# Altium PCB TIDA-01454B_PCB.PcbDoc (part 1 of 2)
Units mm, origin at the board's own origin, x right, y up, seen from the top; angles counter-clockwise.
Board outline 75 x 75 mm, 6 copper layers (Top Copper, Copper Layer 2, Copper Layer 3, Copper Layer 4, Copper Layer 5, Bottom Copper), stack 1.56 mm thick; 207 components, 118 nets, 481 pads, 110 vias.
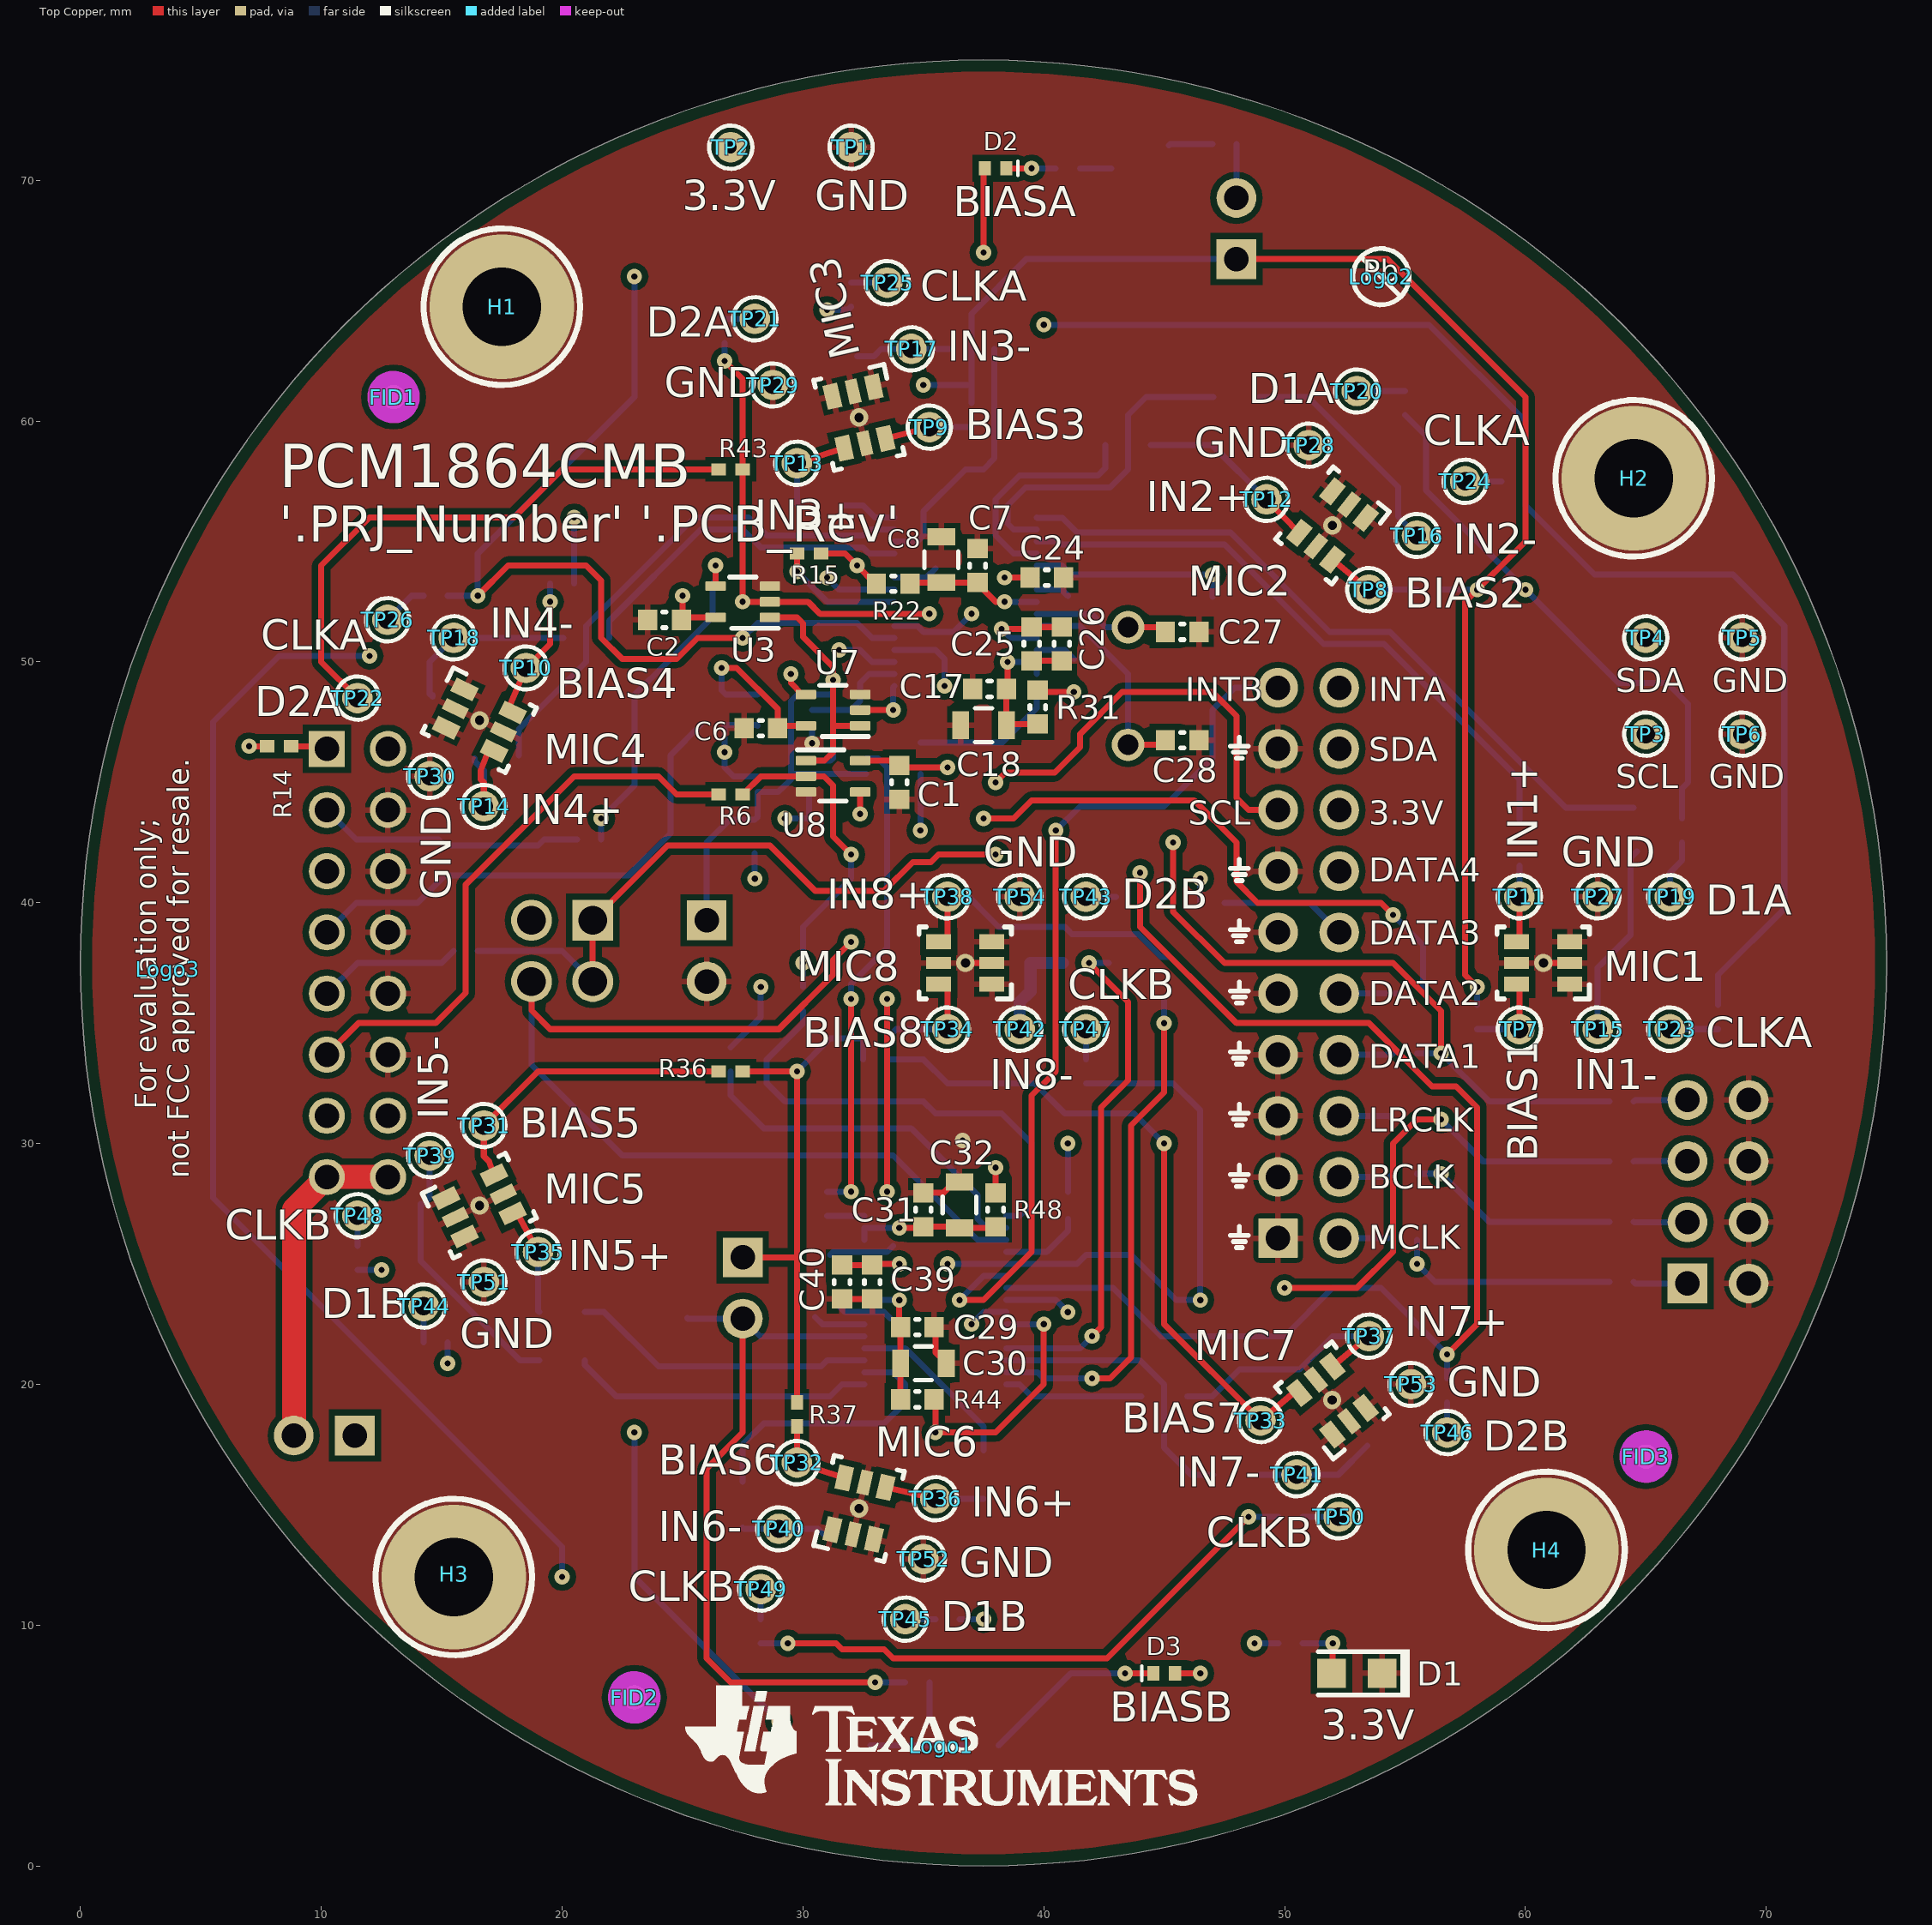
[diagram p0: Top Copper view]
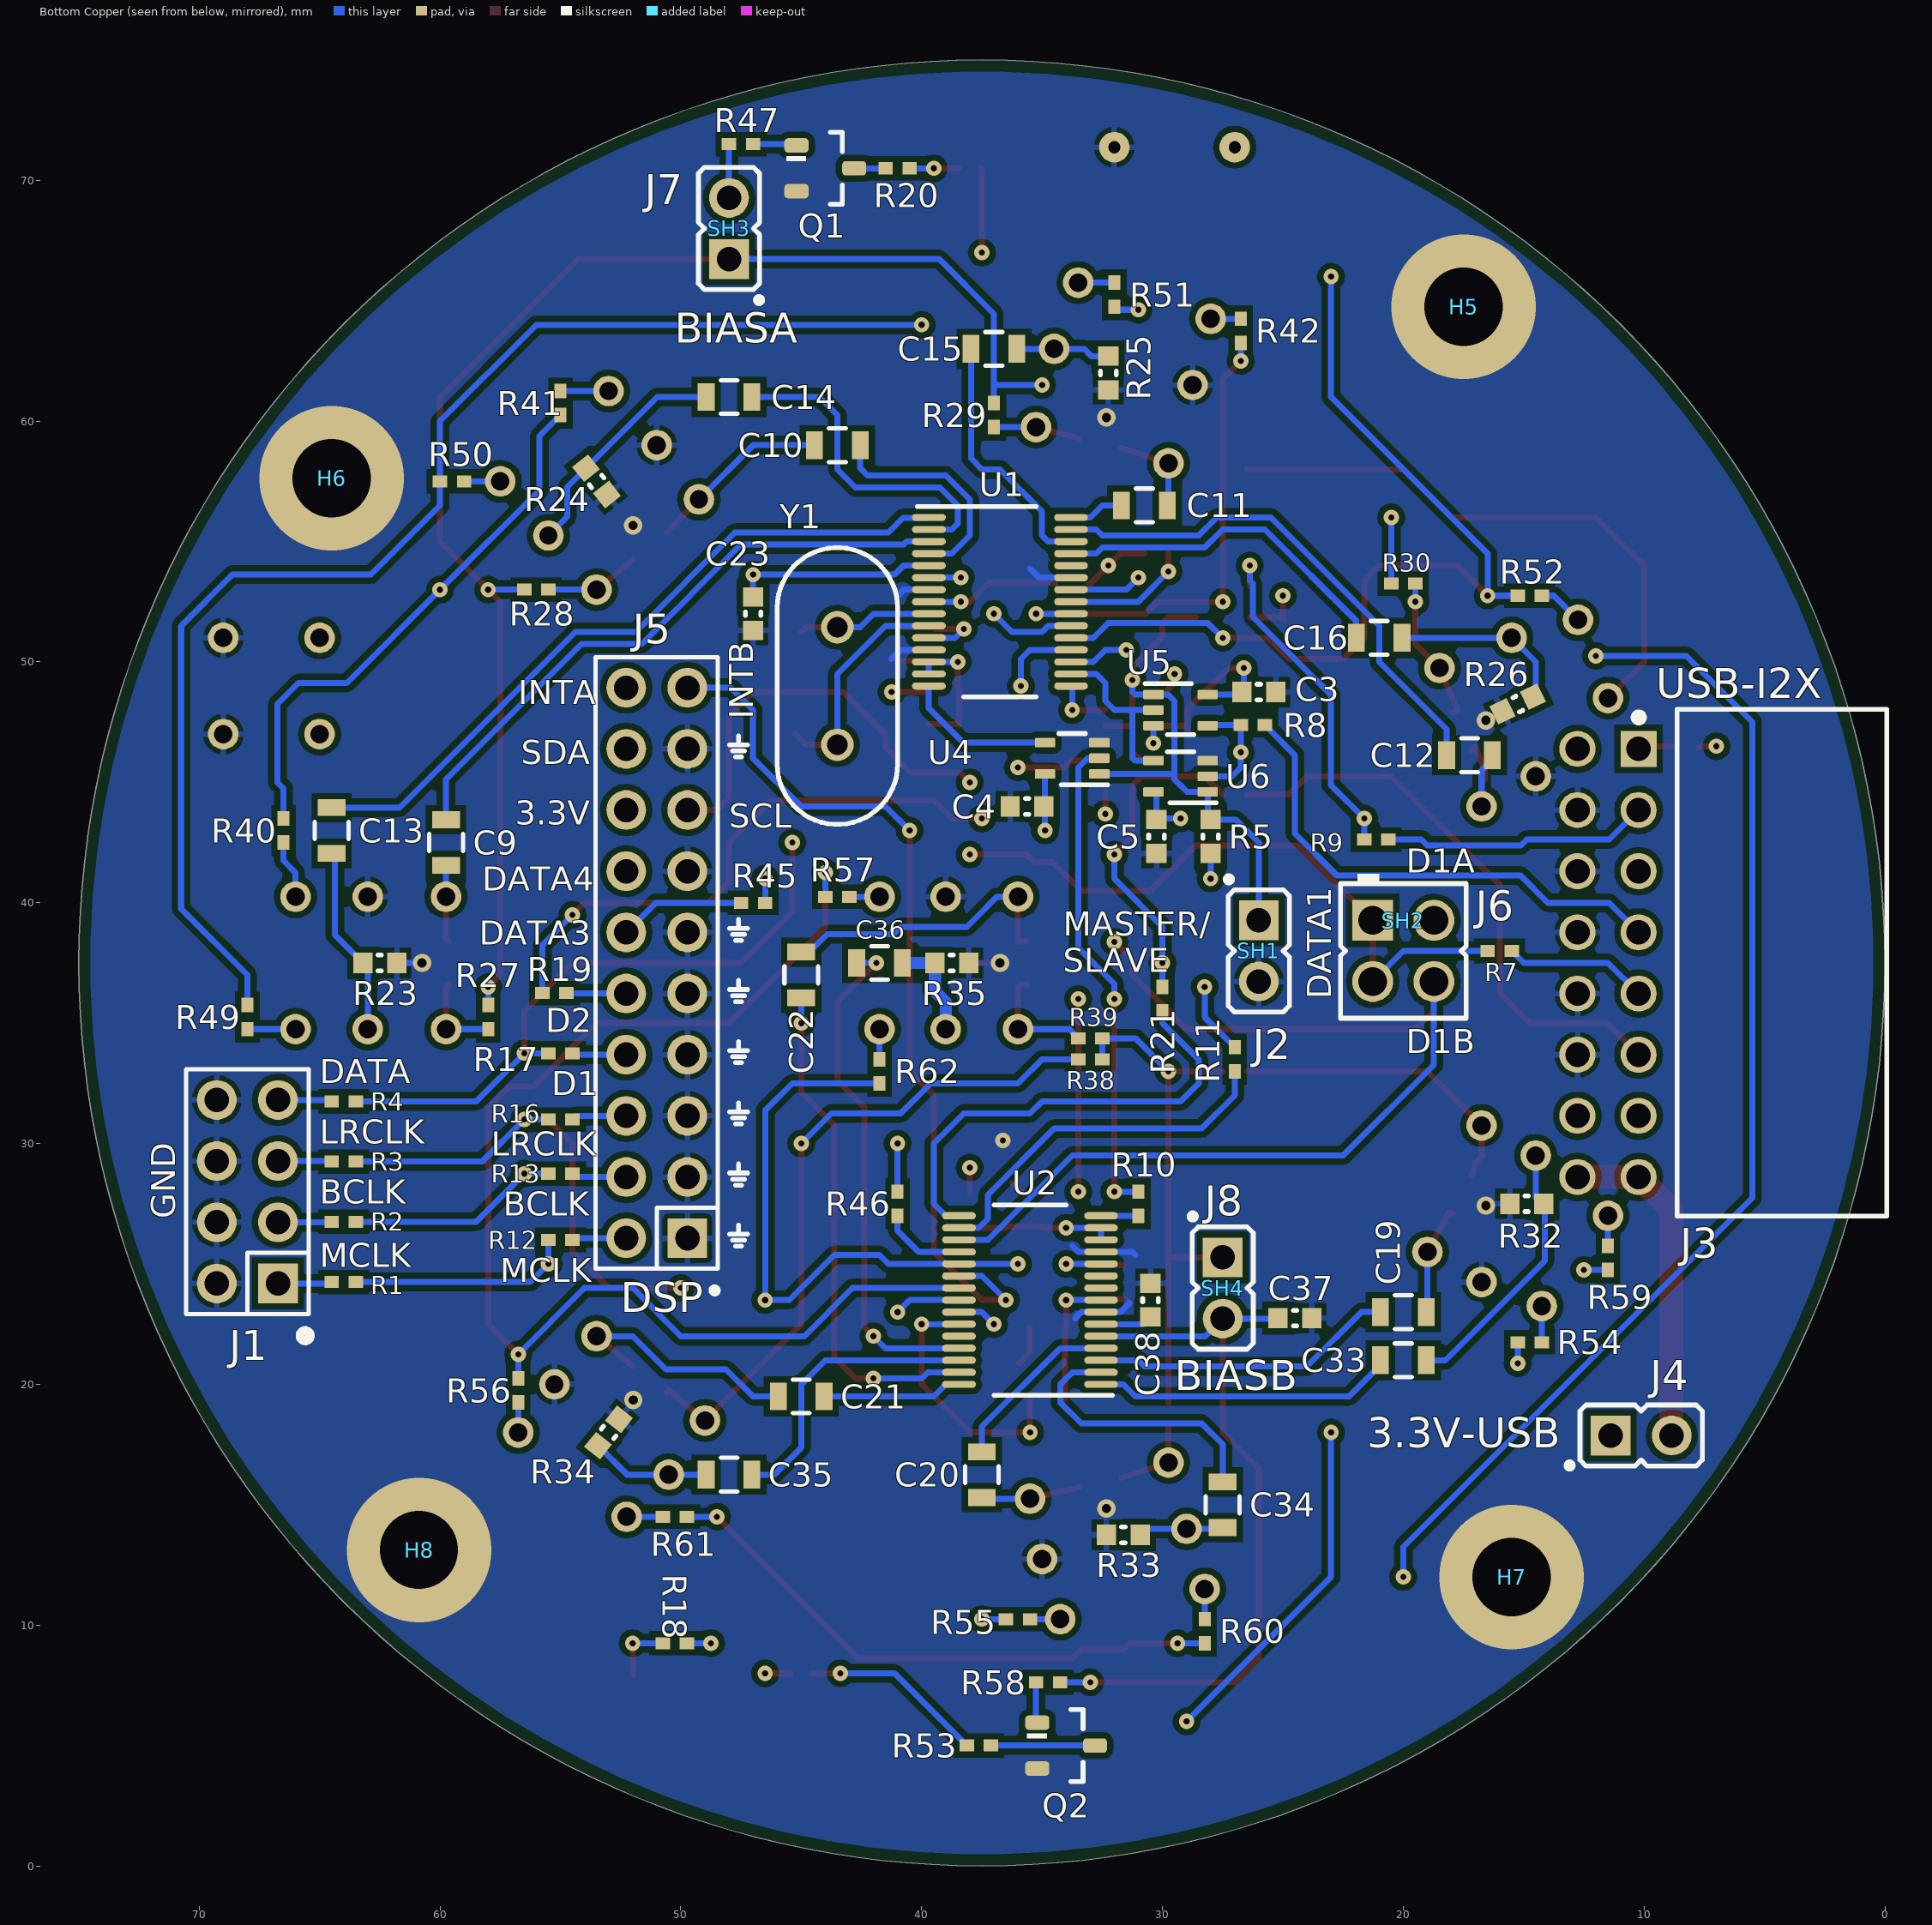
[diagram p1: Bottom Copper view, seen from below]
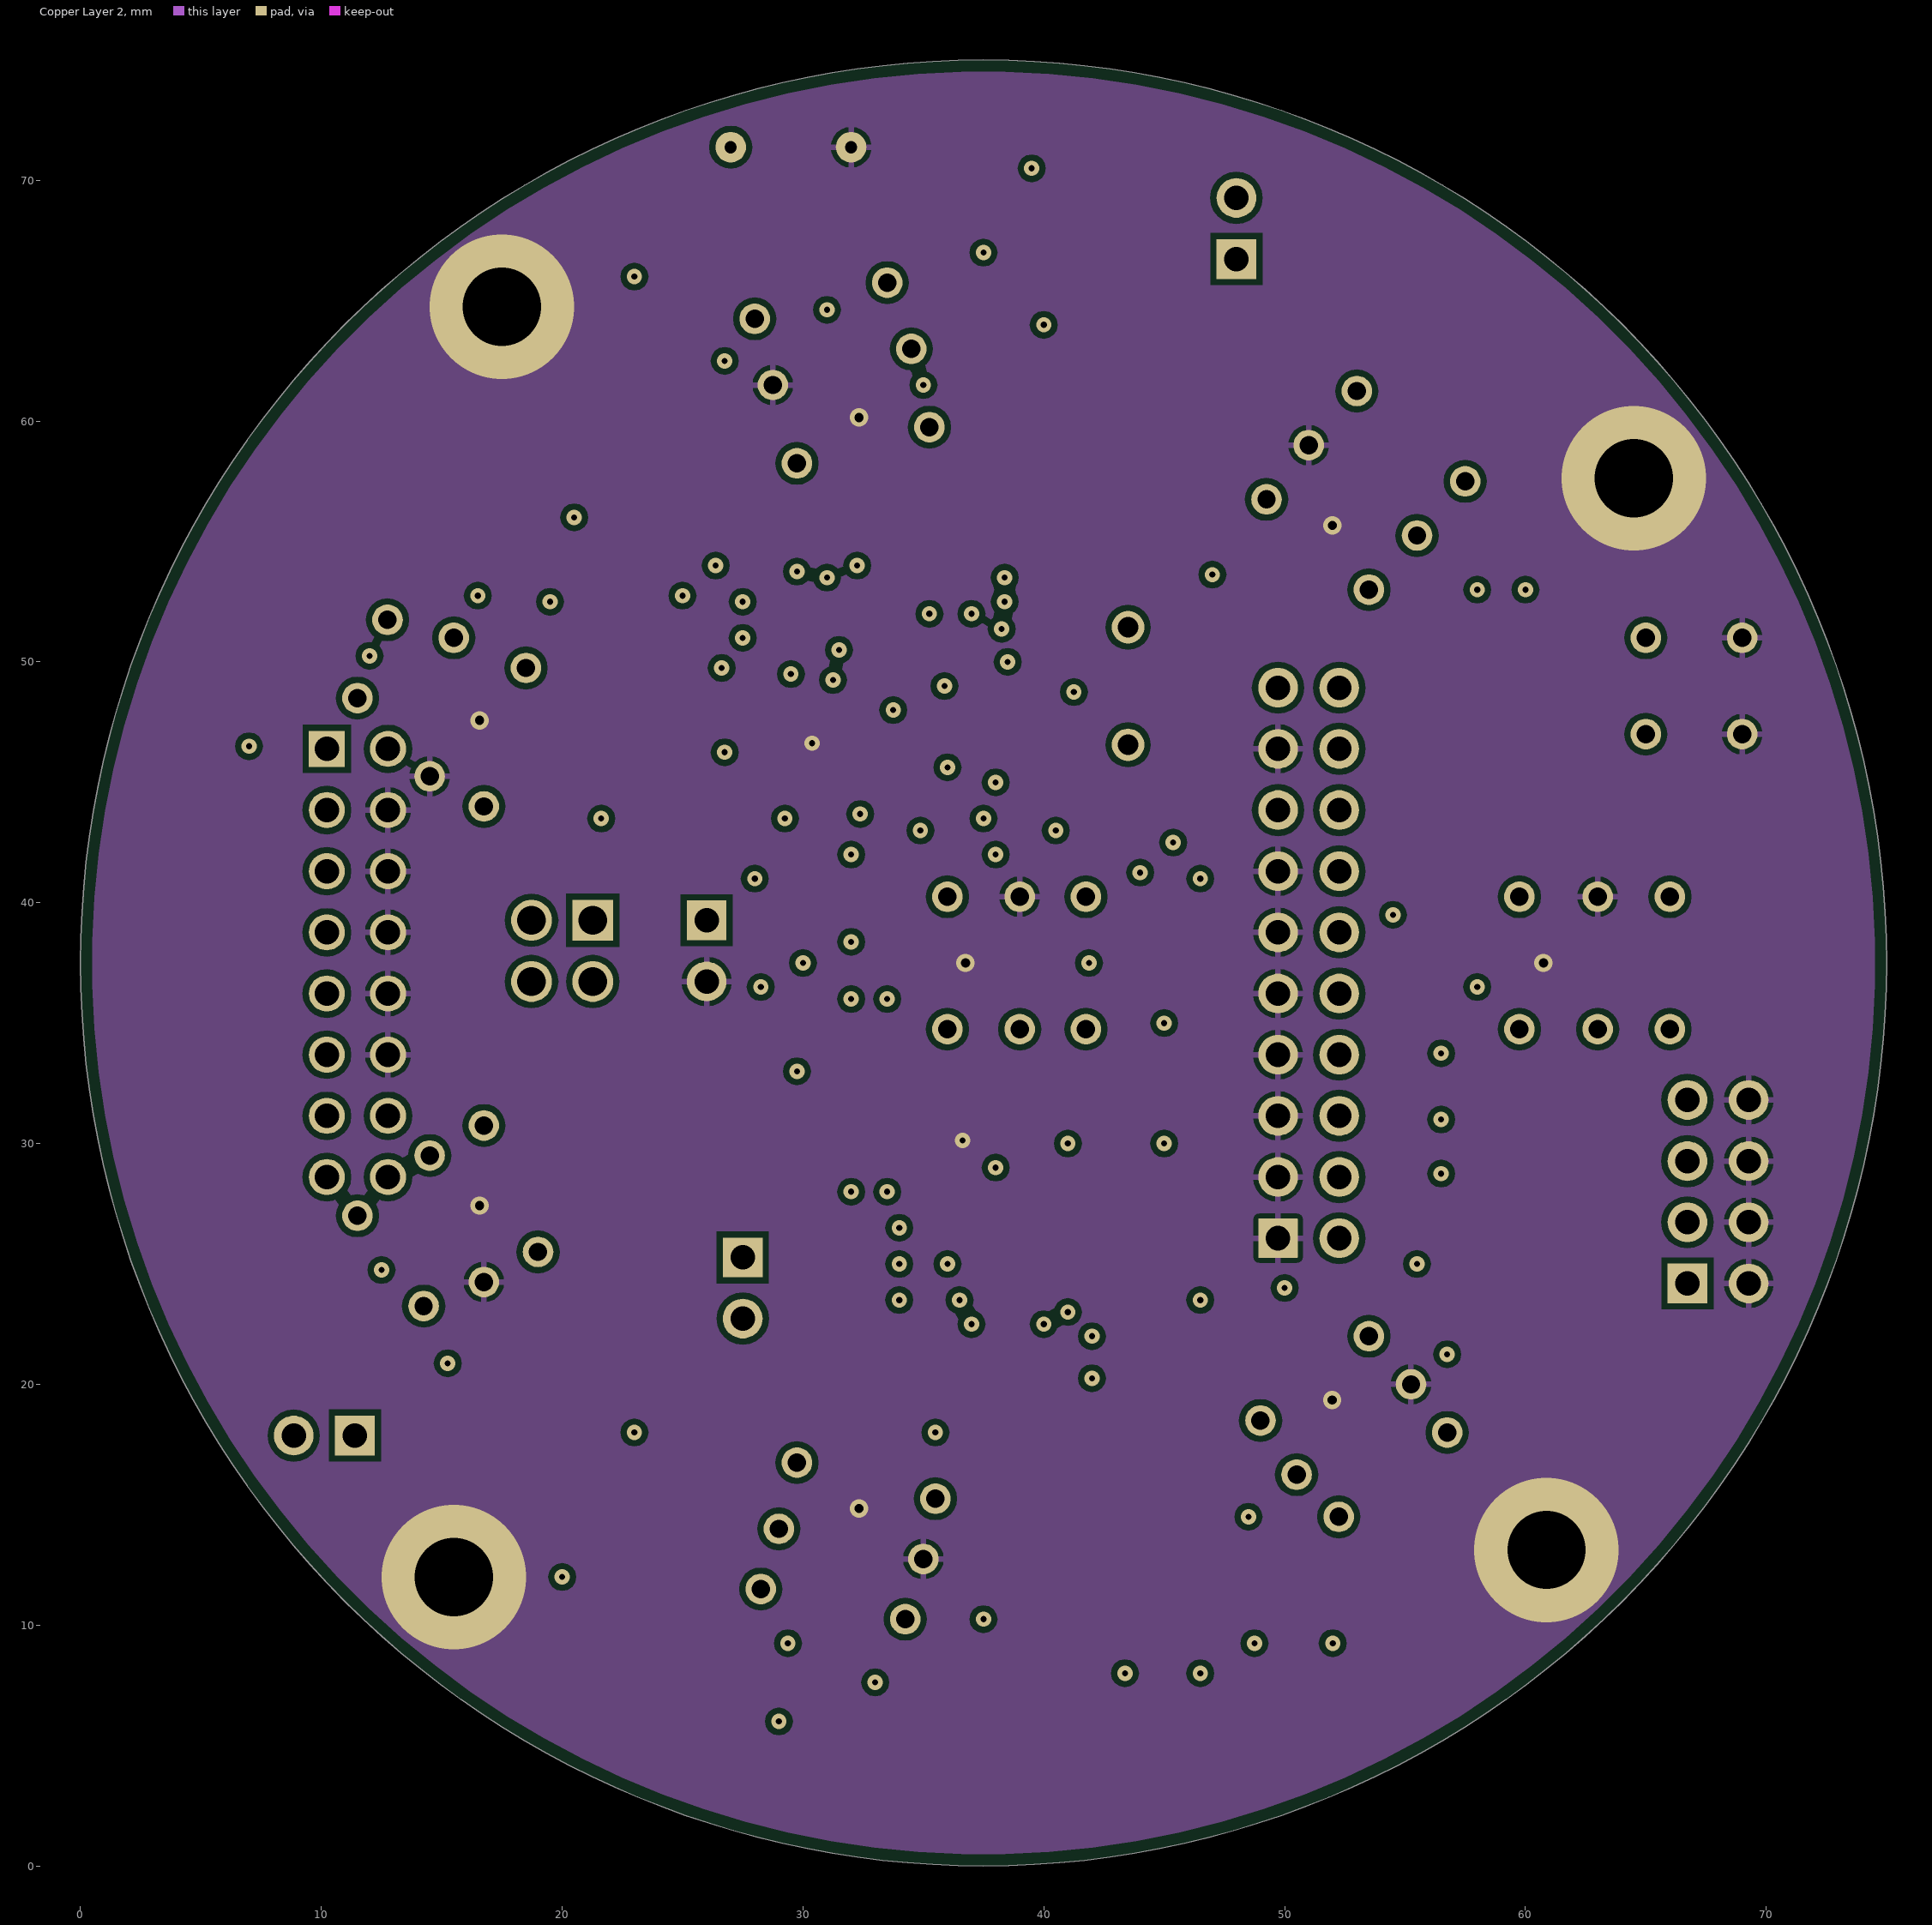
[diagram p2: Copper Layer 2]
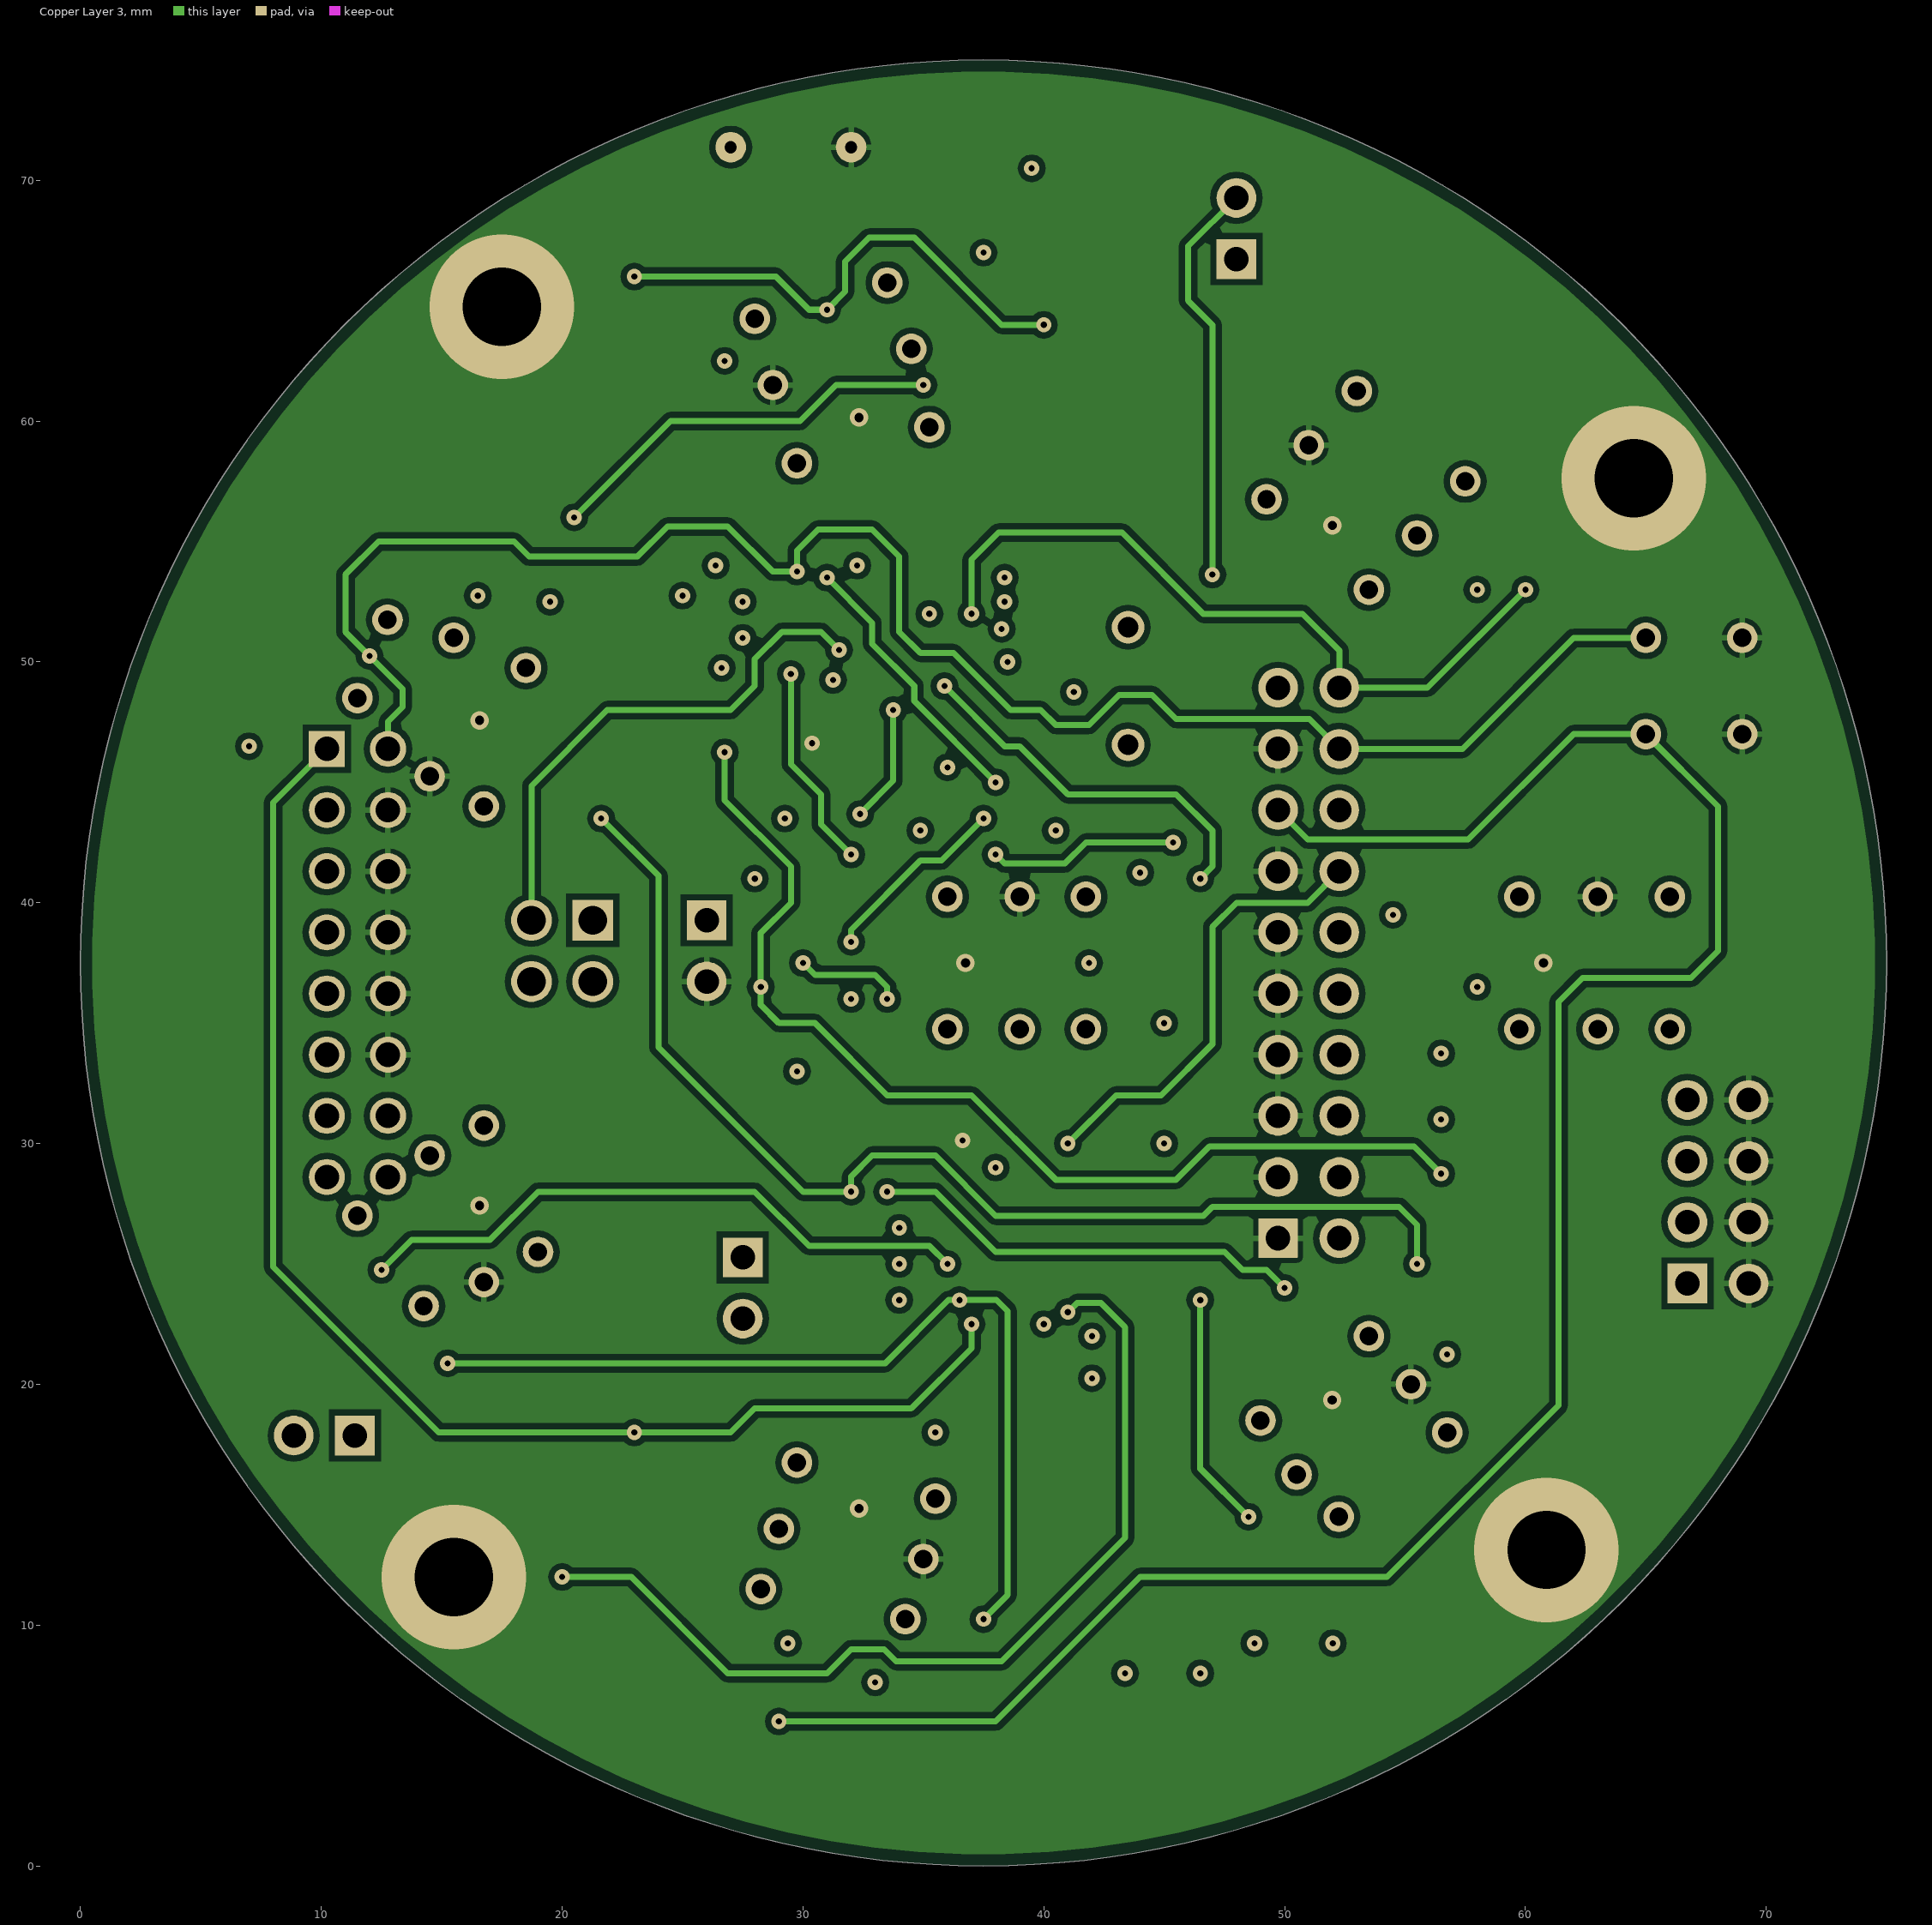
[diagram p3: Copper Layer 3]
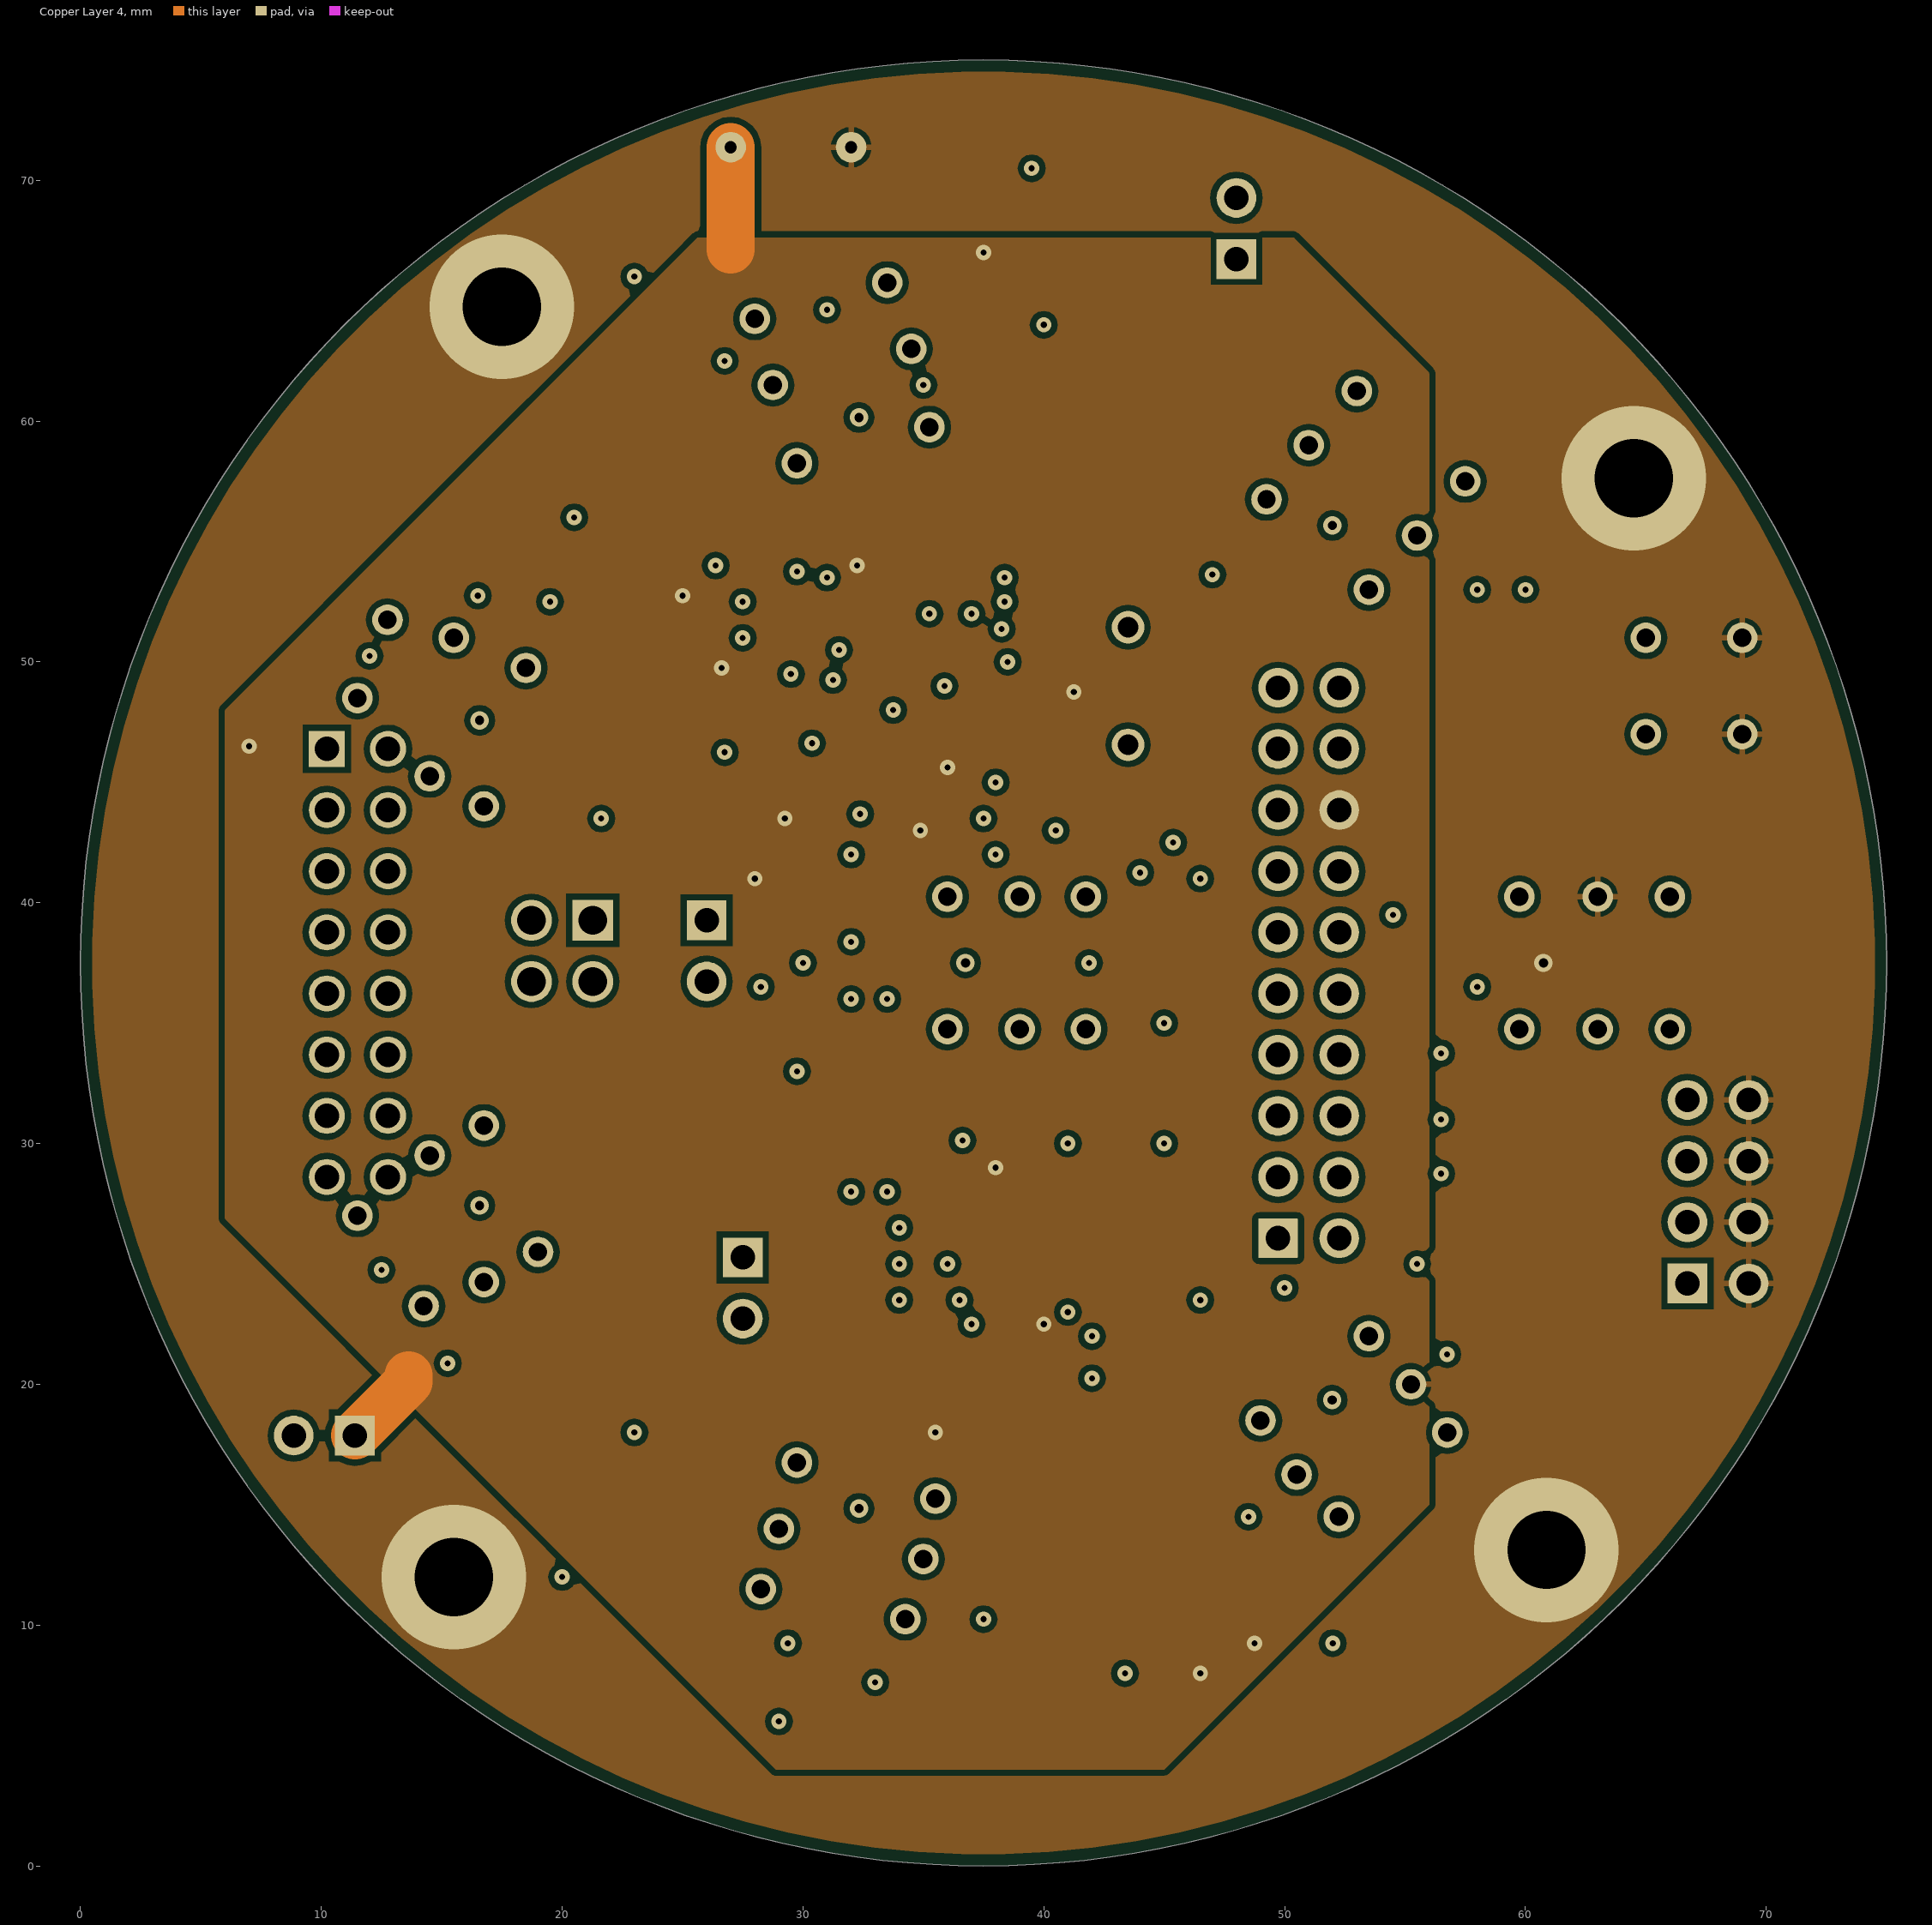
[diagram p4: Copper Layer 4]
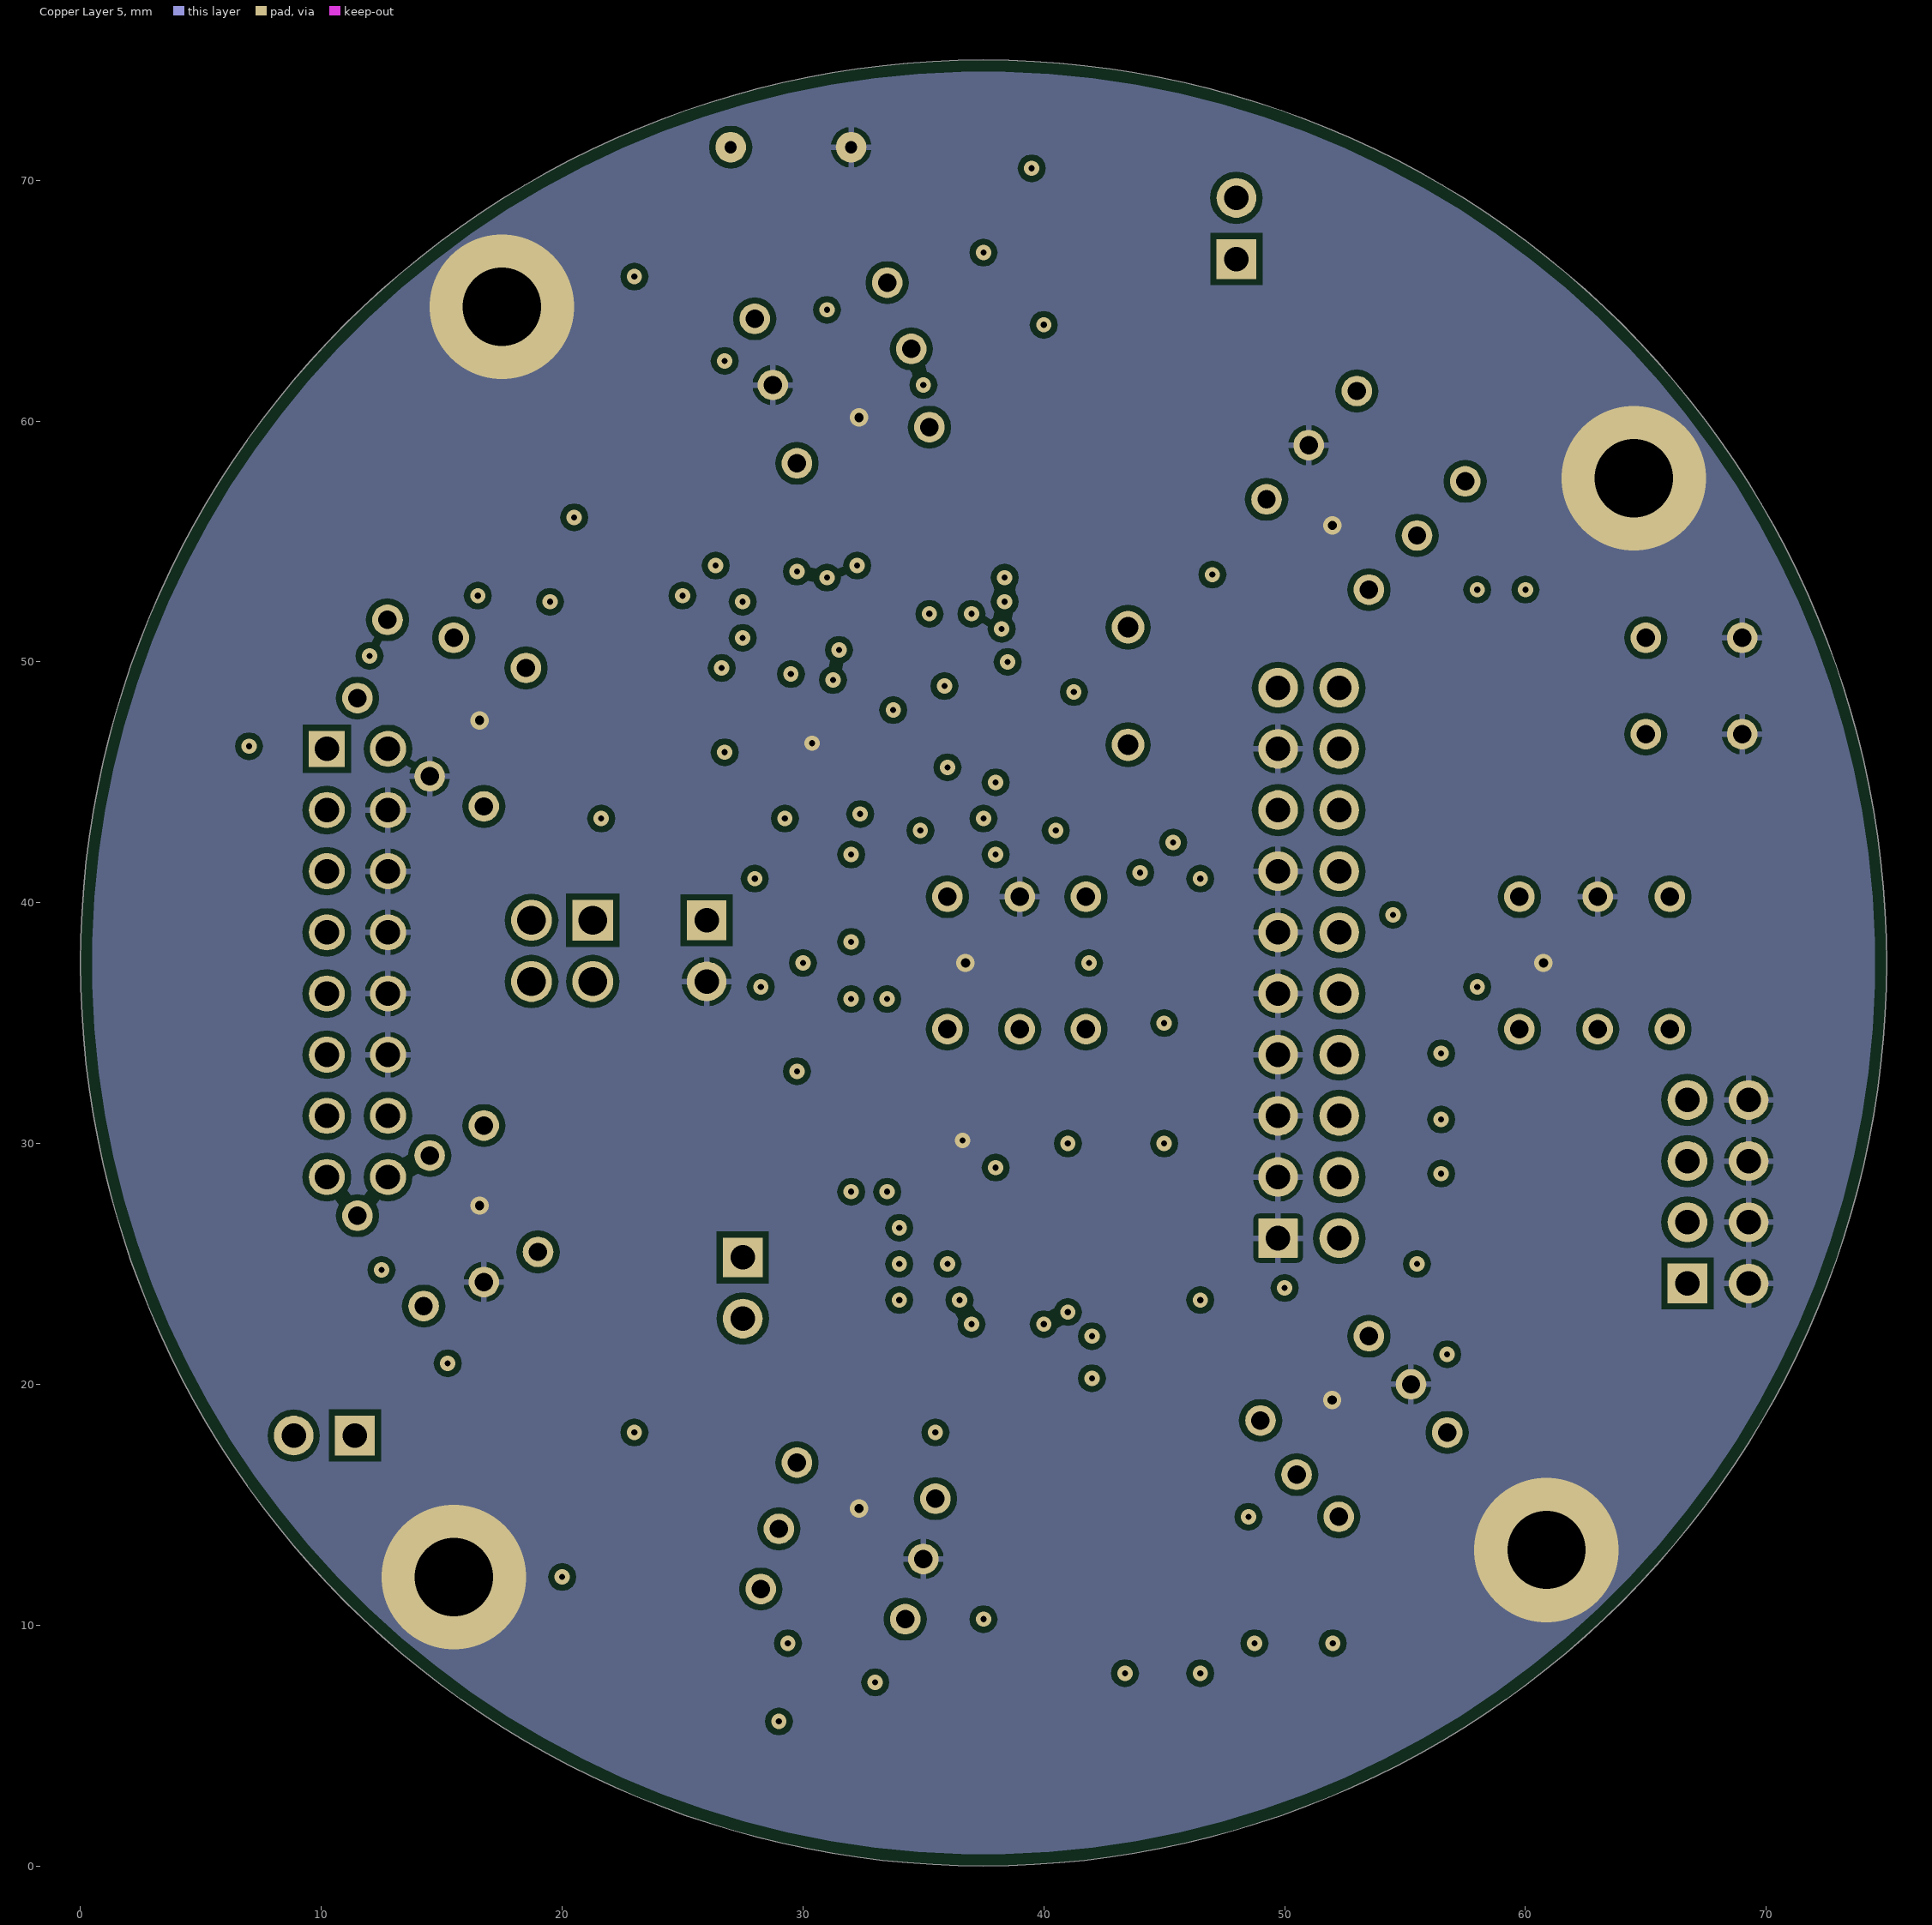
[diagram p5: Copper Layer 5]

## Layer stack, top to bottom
Top Solder Mask: solder mask 0.0127, Solder Resist, Dk 3.5
Top Copper: signal copper 0.0356
Dielectric 1: prepreg 0.1778, FR-4, Dk 4.2
Copper Layer 2: signal copper 0.0356
Dielectric 2: core 0.3556, FR-4, Dk 4.2
Copper Layer 3: signal copper 0.0356
Dielectric 4: prepreg 0.2794, FR-4, Dk 4.2
Copper Layer 4: signal copper 0.0356
Dielectric 5: core 0.3556, FR-4, Dk 4.2
Copper Layer 5: signal copper 0.0356
Dielectric 3: prepreg 0.1778, FR-4, Dk 4.2
Bottom Copper: signal copper 0.0356
Bottom Solder Mask: solder mask 0.0127, Solder Resist, Dk 3.5

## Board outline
37.5,0 cw(c37.5,37.5) 0,37.5 cw(c37.5,37.5) 37.5,75 cw(c37.5,37.5) 75,37.5 cw(c37.5,37.5)

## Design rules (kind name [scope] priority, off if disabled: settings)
AcuteAngle [All] p1: minimum=4.50000000000000E+0001 checktracksonly=FALSE
AssemblyTestPointUsage [All] p1: valid=2
BoardOutlineClearance BoardOutlineClearance_MountingHoles [OnCopper and InComponentClass('Mounting Holes')] p1: gap=1.016
BoardOutlineClearance BoardOutlineClearance_Poly [OnCopper and IsPoly] p2: gap=0.25
BoardOutlineClearance [OnCopper and Not InComponentClass('Logo') and not InComponentClass('FiducialMark') and not InRegion(1000,500,4000,800) and not InPoly] p3: gap=0.25
Clearance Clearance_Keepouts [((IsTrack Or IsArc) And Not InPoly) And IsFree and IsKeepOut vs ((IsTrack Or IsArc) And Not InPoly) And IsFree and IsKeepOut] p1: gap=0
Clearance Clearance_Poly [InPolygon] p2: gap=0.25
Clearance [All] p3: gap=0.2
ComponentClearance ComponentClearance_MountingHoles_FiducialMarks [InComponentClass('Mounting Holes') vs InComponentClass('FiducialMark')] p1: gap=1.27 collisioncheckmode=3 verticalgap=0.254 showdistances=FALSE
ComponentClearance ComponentClearance_Shunt [InComponentClass('Header') vs InComponentClass('Shunt')] p2: gap=0 collisioncheckmode=3 verticalgap=0 showdistances=FALSE
ComponentClearance ComponentClearance_Logo [InComponentClass('Logo')] p3: gap=0 collisioncheckmode=3 verticalgap=0 showdistances=FALSE
ComponentClearance ComponentClearance_ScrewToNut [(HasFootprint('NY PMS 440 0025 PH')) vs (HasFootprint('Keystone_1902C'))] p4: gap=0.127 collisioncheckmode=3 verticalgap=0.254 showdistances=FALSE
ComponentClearance ComponentClearance_MountingHoles [InComponentClass('Hardware') vs InComponentClass('Hardware')] p5: gap=0 collisioncheckmode=3 verticalgap=0 showdistances=FALSE
ComponentClearance ComponentClearance_SmallPassives [HasFootprint('0201*') or HasFootprint('0402*') or HasFootprint('0508') or HasFootprint('0603*') or HasFootprint('0612') or HasFootprint('0805*') or HasFootprint('0815*') or HasFootprint('0830*') or HasFootprint('1206*') or HasFootprint('1210*') or HasFootprint('1808*') or HasFootprint('1812*') or HasFootprint('1825*') or HasFootprint('2010*') or HasFootprint('2220*') or HasFootprint('2225*') or HasFootprint('2512*') or HasFootprint('2728*') or HasFootprint('3518*') or HasFootprint('DCK*') vs HasFootprint('0201*') or HasFootprint('0402*') or HasFootprint('0508') or HasFootprint('0603*') or HasFootprint('0612') or HasFootprint('0805*') or HasFootprint('0815*') or HasFootprint('0830*') or HasFootprint('1206*') or HasFootprint('1210*') or HasFootprint('1808*') or HasFootprint('1812*') or HasFootprint('1825*') or HasFootprint('2010*') or HasFootprint('2220*') or HasFootprint('2225*') or HasFootprint('2512*') or HasFootprint('2728*') or HasFootprint('3518*') or HasFootprint('DCK*')] p6: gap=0.25 collisioncheckmode=3 verticalgap=0 showdistances=FALSE
ComponentClearance ComponentClearance_THtoSMT [IsThruComponent vs IsSMTComponent] p7: gap=0.25 collisioncheckmode=3 verticalgap=0 showdistances=FALSE
ComponentClearance ComponentClearance_THtoTH [IsThruComponent vs IsThruComponent] p8: gap=0.762 collisioncheckmode=3 verticalgap=0.762 showdistances=FALSE
ComponentClearance [All] p9: gap=0.762 collisioncheckmode=3 verticalgap=0.254 showdistances=FALSE
DiffPairsRouting [All] p1: maxlimit=2.54 minlimit=0.254 mostfreqgap=0.254 toplayer_minwidth=0.381 toplayer_maxwidth=0.381 toplayer_prefwidth=0.381 midlayer1_minwidth=0.381 midlayer1_maxwidth=0.381 midlayer1_prefwidth=0.381 midlayer2_minwidth=0.381 midlayer2_maxwidth=0.381 midlayer2_prefwidth=0.381 midlayer3_minwidth=0.381 midlayer3_maxwidth=0.381 midlayer3_prefwidth=0.381 midlayer4_minwidth=0.381 midlayer4_maxwidth=0.381 midlayer4_prefwidth=0.381 bottomlayer_minwidth=0.381 bottomlayer_maxwidth=0.381 bottomlayer_prefwidth=0.381 maxuncoupledlength=25.4
FabricationTestPointUsage TestPointUsage [All] p1: valid=2 allowmultiple=FALSE
FabricationTestpoint Testpoint [All] p1: side=3 testpointundercomponent=TRUE minsize=1.016 maxsize=2.54 preferedsize=1.524 minholesize=0 maxholesize=1.016 preferedholesize=0.813 testpointgrid=0.025 allowsidetop=TRUE allowsidebottom=TRUE usegrid=TRUE gridtolerance=0
FanoutControl Fanout_LCC [IsLCC] p1: bgadir=Out bgaviamode=Centered fanoutstyle=Auto fanoutdirection=Alternating viagrid=0.025 // Fanout_LCC (Default Rule)
FanoutControl Fanout_BGA [IsBGA] p2: bgadir=Out bgaviamode=Centered fanoutstyle=Auto fanoutdirection=Alternating viagrid=0.025 // Fanout_BGA (Default Rule)
FanoutControl Fanout_Default [All] p4: bgadir=Out bgaviamode=Centered fanoutstyle=Auto fanoutdirection=Alternating viagrid=0.025 // Fanout_Default (Default Rule)
FanoutControl Fanout_Small [(CompPinCount < 5)] p5: bgadir=Out bgaviamode=Centered fanoutstyle=Auto fanoutdirection=OutThenIn viagrid=0.025 // Fanout_Small (Default Rule)
HoleSize [All] p1: absolutevalues=TRUE maxlimit=6.375 minlimit=0.2 maxpercent=80.000 minpercent=20.000
MinimumAnnularRing MinimumAnnularRing_ThermalPadVias [IsVia and InAnyComponent] p1: minimumring=0.15
MinimumAnnularRing [All] p2: minimumring=0.127
MinimumSolderMaskSliver MinimumSolderMaskSliver_Logo [InComponentClass('Logo') vs InComponentClass('Logo')] p1: minsoldermaskwidth=0.018
MinimumSolderMaskSliver [All] p2: minsoldermaskwidth=0.089
PlaneConnect [All] p1: planeconnectstyle=Relief reliefexpansion=0.254 reliefentries=4 reliefconductorwidth=0.254 reliefairgap=0.254
PolygonConnect "GND Thermals 0.25mm" [(InComponent('BIAS*') or InComponent('C*') or InComponent('D*') or InComponent('GND*') or InComponent('I2S*') or InComponent('J*') or InComponent('MIC*') or InComponent('R*') or InComponent('TP*') or InComponent('USB-I2X')) vs InNet('GND')] p1: connectstyle=Relief reliefconductorwidth=0.25 reliefentries=4 polygonreliefangle="90 Angle" airgapwidth=0.2
PolygonConnect PreFlood [All] p2: connectstyle=Direct reliefconductorwidth=0.254 reliefentries=4 polygonreliefangle="90 Angle" airgapwidth=0.254
RoutingVias ThermalPadVias [IsVia and InAnyComponent] p1: holewidth=0.2 width=0.5 viastyle="Through Hole" minholewidth=0.2 minwidth=0.5 maxholewidth=0.33 maxwidth=0.6
RoutingVias [All] p2: holewidth=0.254 width=0.635 viastyle="Through Hole" minholewidth=0.254 minwidth=0.508 maxholewidth=3.25 maxwidth=6
SilkToBoardRegionClearance [Not ((IsComment or IsDesignator) And (Hide <> 'False')) and not InRegion(1000,500,4000,800)] p1:
SilkToSilkClearance SilkToSilkClearance_Pb-FreeLogo [(HasFootprint('Pb-Free_Overlay_Medium') OR HasFootprint('Pb-Free_Overlay_Small')) vs (HasFootprint('Pb-Free_Overlay_Medium') OR HasFootprint('Pb-Free_Overlay_Small'))] p1: silktosilkclearance=0
SilkToSilkClearance [All] p2: silktosilkclearance=0.127
SilkToSolderMaskClearance SilkToComponentPadClearance [IsPad and InAnycomponent] p1: minsilkscreentomaskgap=0.127 clearancetoexposedcopper=TRUE
SilkToSolderMaskClearance "Silk to Solder Mask Opening" [All] p2: minsilkscreentomaskgap=0.127 clearancetoexposedcopper=FALSE
SolderMaskExpansion [All] p1: expansion=0.05
Width [All] p1: maxlimit=2.54 minlimit=0.152 preferedwidth=0.254 checkconnectedcopper=TRUE
15 further rules are at their usual default settings.

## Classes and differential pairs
component class Shunt: SH1 SH2 SH3 SH4
component class TIDA-01454B_Digital-IO: C1 C2 C3 C4 C5 C6 J1 J2 J3 J4 J5 J6 R1 R2 R3 R4 R5 R6 R7 R8 R9 R10 R11 R12 R13 R14 R15 R16 R17 R19 R21 R45 R46 TP1 TP2 TP3 TP4 TP5 TP6 U3 U4 U5 U6 U7 U8
component class Hardware: H1 H2 H3 H4 H5 H6 H7 H8
component class AssemblyNote: ZZ1 ZZ2 ZZ3
component class FiducialMark: FID1 FID2 FID3
component class TIDA-01454B_Hardware: FID1 FID2 FID3 H1 H2 H3 H4 H5 H6 H7 H8 Logo1 Logo2 Logo3 SH1 SH2 SH3 SH4 ZZ1 ZZ2 ZZ3
component class Logo: Logo1
component class Header: J1 J2 J4 J5 J6 J7 J8 J?
component class TIDA-01454B_Main-IO: C7 C8 C9 C10 C11 C12 C13 C14 C15 C16 C17 C18 C19 C20 C21 C22 C23 C24 C25 C26 C27 C28 C29 C30 C31 C32 C33 C34 C35 C36 C37 C38 C39 C40 D1 D2 D3 J7 J8 MIC1 MIC2 MIC3 MIC4 MIC5 MIC6 MIC7 MIC8 Q1 Q2 R18 R20 R22 R23 R24 R25 R26 R27 R28 R29 R30 R31 R32 R33 R34 R35 R36 R37 R38 R39 R40 R41 R42 R43 R44 R47 R48 R49 R50 R51 R52 R53 R54 R55 R56 R57 R58 R59 R60 R61 R62 TP7 TP8 TP9 TP10 TP11 TP12 TP13 TP14 TP15 TP16 TP17 TP18 TP19 TP20 TP21 TP22 TP23 TP24 TP25 TP26 TP27 TP28 TP29 TP30 TP31 TP32 TP33 TP34 TP35 TP36 TP37 TP38 TP39 TP40 TP41 TP42 TP43 TP44 TP45 TP46 TP47 TP48 TP49 TP50 TP51 TP52 TP53 TP54 U1 U2 Y1

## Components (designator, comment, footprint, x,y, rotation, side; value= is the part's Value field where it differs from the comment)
C1 "GRM188R71C104KA01D" 0603L 34,45 r90 top
C2 "GRM188R71C104KA01D" 0603L 24.25,51.75 r0 top
C3 "GRM188R71C104KA01D" 0603L 26,48.75 r0 bottom
C4 "GRM188R71C104KA01D" 0603L 35.625,44 r180 bottom
C5 "GRM188R71C104KA01D" 0603L 30.25,42.75 r90 bottom
C6 "GRM188R71C104KA01D" 0603L 28.25,47.25 r0 top
C7 "GRM188R71C104KA01D" 0603L 37.25,54 r270 top
C8 "GRM21BR71A106KE51K" 0805_KTR 35.75,54.25 r270 top
C9 "GRM21BR71A106KE51K" 0805_KTR 59.75,42.5 r270 bottom
C10 "GRM21BR71A106KE51K" 0805_KTR 43.5,59 r0 bottom
C11 "GRM21BR71A106KE51K" 0805_KTR 30.75,56.5 r180 bottom
C12 "GRM21BR71A106KE51K" 0805_KTR 17.25,46.125 r180 bottom
C13 "GRM21BR71A106KE51K" 0805_KTR 64.5,43 r270 bottom
C14 "GRM21BR71A106KE51K" 0805_KTR 48,61 r0 bottom
C15 "GRM21BR71A106KE51K" 0805_KTR 37,63 r180 bottom
C16 "GRM21BR71A106KE51K" 0805_KTR 21,51 r180 bottom
C17 "GRM188R71C104KA01D" 0603L 37.75,48.875 r0 top
C18 "GRM21BR71A106KE51K" 0805_KTR 37.5,47.375 r0 top
C19 "GRM21BR71A106KE51K" 0805_KTR 20,23 r180 bottom
C20 "GRM21BR71A106KE51K" 0805_KTR 37.5,16.25 r270 bottom
C21 "GRM21BR71A106KE51K" 0805_KTR 45,19.5 r0 bottom
C22 "GRM21BR71A106KE51K" 0805_KTR 45,37 r90 bottom
C23 "GRM188R71C104KA01D" 0603L 47,52 r90 bottom
C24 "GRM188R71C105KA12D" 0603L 40.125,53.5 r0 top
C25 "GRM188R71C104KA01D" 0603L 39.5,50.75 r90 top
C26 "GRM188R71C105KA12D" 0603L 40.75,50.75 r270 top
C27 "GRM1885C1H180JA01D" 0603L 45.75,51.25 r0 top
C28 "GRM1885C1H180JA01D" 0603L 45.75,46.75 r0 top
C29 "GRM188R71C104KA01D" 0603L 34.75,22.375 r180 top
C30 "GRM21BR71A106KE51K" 0805_KTR 35,20.875 r180 top
C31 "GRM188R71C104KA01D" 0603L 35,27.25 r270 top
C32 "GRM21BR71A106KE51K" 0805_KTR 36.5,27.45 r270 top
C33 "GRM21BR71A106KE51K" 0805_KTR 20,21 r180 bottom
C34 "GRM21BR71A106KE51K" 0805_KTR 27.5,15 r270 bottom
C35 "GRM21BR71A106KE51K" 0805_KTR 48,16.25 r0 bottom
C36 "GRM21BR71A106KE51K" 0805_KTR 41.75,37.5 r180 bottom
C37 "GRM188R71C104KA01D" 0603L 24.5,22.75 r0 bottom
C38 "GRM188R71C105KA12D" 0603L 30.5,23.5 r90 bottom
C39 "GRM188R71C104KA01D" 0603L 32.875,24.25 r90 top
C40 "GRM188R71C105KA12D" 0603L 31.625,24.25 r270 top
D1 "3.3V" LED_LTST-C171 53,8 r0 top
D2 "BIASA" LED_SMLP12_BLUE 38,70.5 r0 top
D3 "BIASB" LED_SMLP12_BLUE 45,8 r180 top
FID1 "Fiducial" Fiducial10-20 13,61 r0 top
FID2 "Fiducial" Fiducial10-20 23,7 r0 top
FID3 "Fiducial" Fiducial10-20 65,17 r0 top
H1 "M3" BuildingFastener_MPMS_003_0005_PH 17.5,64.75 r0 top
H2 "M3" BuildingFastener_MPMS_003_0005_PH 64.5,57.625 r0 top
H3 "M3" BuildingFastener_MPMS_003_0005_PH 15.5,12.125 r0 top
H4 "M3" BuildingFastener_MPMS_003_0005_PH 60.875,13.125 r0 top
H5 "24438" Keystone24438 17.5,64.75 r180 bottom
H6 "24438" Keystone24438 64.5,57.625 r180 bottom locked
H7 "24438" Keystone24438 15.5,12 r180 bottom
H8 "24438" Keystone24438 60.875,13.125 r180 bottom
J1 "DNP" CONN_PEC04DAAN 68,28 r90 bottom
J2 "Master/Slave" Sullins_PBC02SAAN 26,38 r180 bottom
J3 "USB-I2X" Sullins_PPPC082LJBN-RC 11.5,37.5 r90 bottom locked
J4 "3.3V-USB" Sullins_PBC02SAAN 10.125,17.875 r90 bottom
J5 "DSP" TSW-110-07-G-D 51,37.5 r90 bottom locked
J6 "PBC02DAAN" Sullins_PxC02DAAN 20,38 r180 bottom
J7 "BIASA" Sullins_PBC02SAAN 48,68 r0 bottom
J8 "BIASB" Sullins_PBC02SAAN 27.5,24 r180 bottom
Logo1 "Texas Instruments" TI_Stacked_Overlay_Small 35.75,5 r0 top
Logo2 "Pb-Free Symbol" Pb-Free_Overlay_Small 54,66 r0 top
Logo3 "FCC disclaimer" FCC_disclaimer_stacked 3.625,37.25 r90 top
MIC1 "SPH1642HT5H-1" Knowles_SPH1642HT5H-1 61.5,37.5 r180 top locked
MIC2 "SPH1642HT5H-1" Knowles_SPH1642HT5H-1 52.464,56.264 r231.43 top locked
MIC3 "SPH1642HT5H-1" Knowles_SPH1642HT5H-1 32.159,60.898 r282.86 top locked
MIC4 "SPH1642HT5H-1" Knowles_SPH1642HT5H-1 15.877,47.913 r334.29 top locked
MIC5 "SPH1642HT5H-1" Knowles_SPH1642HT5H-1 15.877,27.086 r25.72 top locked
MIC6 "SPH1642HT5H-1" Knowles_SPH1642HT5H-1 32.16,14.102 r77.14 top locked
MIC7 "SPH1642HT5H-1" Knowles_SPH1642HT5H-1 52.465,18.737 r128.57 top locked
MIC8 "SPH1642HT5H-1" Knowles_SPH1642HT5H-1 37.5,37.5 r180 top locked
Q1 "MMBT2222A" SOT-23 44,70.5 r180 bottom
Q2 "MMBT2222A" SOT-23 34,5 r180 bottom
R1 "RC0402FR-0749R9L" 0402L 64,24.25 r0 bottom
R2 "RC0402FR-0749R9L" 0402L 64,26.75 r0 bottom
R3 "RC0402FR-0749R9L" 0402L 64,29.25 r0 bottom
R4 "RC0402FR-0749R9L" 0402L 64,31.75 r0 bottom
R5 "ERJ-3EKF1002V" 0603L 28,42.75 r270 bottom
R6 "RC0402FR-0749R9L" 0402L 27,44.5 r180 top
R7 "RC0402FR-0749R9L" 0402L 16,38 r180 bottom
R8 "RC0402FR-0749R9L" 0402L 26.25,47.375 r180 bottom
R9 "RC0402FR-0749R9L" 0402L 21.125,42.625 r180 bottom
R10 "RC0402FR-0749R9L" 0402L 31,27.5 r90 bottom
R11 "RC0402FR-0749R9L" 0402L 27,33.5 r90 bottom
R12 "RC0402FR-0749R9L" 0402L 55,26 r180 bottom
R13 "RC0402FR-0749R9L" 0402L 55,28.75 r180 bottom
R14 "CRCW04022K21FKED" 0402L 8.25,46.5 r0 top
R15 "CRCW04022K21FKED" 0402L 30.25,54.5 r180 top
R16 "RC0402FR-0749R9L" 0402L 55,31 r180 bottom
R17 "RC0402FR-0749R9L" 0402L 55,33.75 r180 bottom
R18 "CRCW0402360RJNED" 0402L 50.25,9.25 r180 bottom
R19 "RC0402FR-0749R9L" 0402L 55.25,36.25 r180 bottom
R20 "ERJ-2RKF1000X" 0402L 41,70.5 r0 bottom
R21 "RC0402FR-0749R9L" 0402L 30,36 r90 bottom
R22 "CRCW06030000Z0EA" 0603L 33.75,53.25 r0 top
R23 "CRCW06030000Z0EA" 0603L 62.5,37.5 r180 bottom
R24 "CRCW06030000Z0EA" 0603L 53.5,57.5 r231.43 bottom
R25 "CRCW06030000Z0EA" 0603L 32.25,62 r270 bottom
R26 "CRCW06030000Z0EA" 0603L 15.25,48.25 r334.29 bottom
R27 "CRCW04022K21FKED" 0402L 58,35.25 r270 bottom
R28 "CRCW04022K21FKED" 0402L 56,53 r180 bottom
R29 "CRCW04022K21FKED" 0402L 37,60.25 r270 bottom
R30 "CRCW04022K21FKED" 0402L 20,53.25 r180 bottom
R31 "CRCW06030000Z0EA" 0603L 39.75,48.125 r270 top
R32 "CRCW06030000Z0EA" 0603L 14.875,27.5 r0 bottom
R33 "CRCW06030000Z0EA" 0603L 31.625,13.75 r0 bottom
R34 "CRCW06030000Z0EA" 0603L 53,18 r128.57 bottom locked
R35 "CRCW06030000Z0EA" 0603L 38.75,37.5 r180 bottom
R36 "CRCW04022K21FKED" 0402L 27,33 r180 top
R37 "CRCW04022K21FKED" 0402L 29.75,18.75 r270 top
R38 "CRCW04022K21FKED" 0402L 33,33.5 r0 bottom
R39 "CRCW04022K21FKED" 0402L 33,34.375 r0 bottom
R40 "RC0402FR-0749R9L" 0402L 66.5,43 r270 bottom
R41 "RC0402FR-0749R9L" 0402L 55,60.75 r90 bottom
R42 "RC0402FR-0749R9L" 0402L 26.75,63.75 r90 bottom
R43 "RC0402FR-0749R9L" 0402L 27,58 r180 top
R44 "CRCW06030000Z0EA" 0603L 34.75,19.375 r180 top
R45 "RC0402FR-0749R9L" 0402L 47,40 r0 bottom
R46 "RC0402FR-0749R9L" 0402L 41,27.5 r90 bottom
R47 "CRCW04022K15FKED" 0402L 47.5,71.5 r0 bottom
R48 "CRCW06030000Z0EA" 0603L 38,27.25 r270 top
R49 "RC0402FR-0749R9L" 0402L 68,35.25 r270 bottom
R50 "RC0402FR-0749R9L" 0402L 59.5,57.5 r180 bottom
R51 "RC0402FR-0749R9L" 0402L 32,65.25 r90 bottom
R52 "RC0402FR-0749R9L" 0402L 14.75,52.75 r180 bottom
R53 "ERJ-2RKF1000X" 0402L 37.625,5 r180 bottom
R54 "RC0402FR-0749R9L" 0402L 14.75,21.75 r180 bottom
R55 "RC0402FR-0749R9L" 0402L 36,10.25 r180 bottom
R56 "RC0402FR-0749R9L" 0402L 56.75,19.75 r270 bottom
R57 "RC0402FR-0749R9L" 0402L 43.5,40.25 r180 bottom
R58 "CRCW04022K15FKED" 0402L 34.75,7.625 r180 bottom
R59 "RC0402FR-0749R9L" 0402L 11.5,25.25 r90 bottom
R60 "RC0402FR-0749R9L" 0402L 28.25,9.75 r90 bottom
R61 "RC0402FR-0749R9L" 0402L 50.25,14.5 r0 bottom
R62 "RC0402FR-0749R9L" 0402L 41.75,33 r90 bottom
SH1 "SNT-100-BK-G" SNT-100-BK-G 26,38 r90 bottom
SH2 "SNT-100-BK-G" SNT-100-BK-G 20,39.25 r180 bottom
SH3 "SNT-100-BK-G" SNT-100-BK-G 48,68 r90 bottom
SH4 "SNT-100-BK-G" SNT-100-BK-G 27.5,24 r270 bottom
TP1 "GND" TestPoint_50x20-TH 32,71.375 r90 top
TP2 "3.3V" TestPoint_50x20-TH 27,71.375 r90 top
TP3 "SCL" TestPoint_50x30-TH 65,47 r0 top
TP4 "SDA" TestPoint_50x30-TH 65,51 r0 top
TP5 "GND" TestPoint_50x30-TH 69,51 r0 top
TP6 "GND" TestPoint_50x30-TH 69,47 r0 top
TP7 "BIAS1" TestPoint_50x30-TH 59.75,34.75 r90 top
TP8 "BIAS2" TestPoint_50x30-TH 53.5,53 r90 top
TP9 "BIAS3" TestPoint_50x30-TH 35.25,59.75 r90 top
TP10 "BIAS4" TestPoint_50x30-TH 18.5,49.75 r90 top
TP11 "IN1+" TestPoint_50x30-TH 59.75,40.25 r0 top
TP12 "IN2+" TestPoint_50x30-TH 49.25,56.75 r90 top
TP13 "IN3+" TestPoint_50x30-TH 29.75,58.25 r90 top
TP14 "IN4+" TestPoint_50x30-TH 16.75,44 r90 top
TP15 "IN1-" TestPoint_50x30-TH 63,34.75 r0 top
TP16 "IN2-" TestPoint_50x30-TH 55.5,55.25 r90 top
TP17 "IN3-" TestPoint_50x30-TH 34.5,63 r90 top
TP18 "IN4-" TestPoint_50x30-TH 15.5,51 r90 top
TP19 "D1A" TestPoint_50x30-TH 66,40.25 r0 top
TP20 "D1A" TestPoint_50x30-TH 53,61.25 r0 top
TP21 "D2A" TestPoint_50x30-TH 28,64.25 r0 top
TP22 "D2A" TestPoint_50x30-TH 11.5,48.5 r0 top
TP23 "CLKA" TestPoint_50x30-TH 66,34.75 r0 top
TP24 "CLKA" TestPoint_50x30-TH 57.5,57.5 r90 top
TP25 "CLKA" TestPoint_50x30-TH 33.5,65.75 r0 top
TP26 "CLKA" TestPoint_50x30-TH 12.75,51.75 r90 top
TP27 "GND" TestPoint_50x30-TH 63,40.25 r0 top
TP28 "GND" TestPoint_50x30-TH 51,59 r0 top
TP29 "GND" TestPoint_50x30-TH 28.75,61.5 r0 top
TP30 "GND" TestPoint_50x30-TH 14.5,45.25 r0 top
TP31 "BIAS5" TestPoint_50x30-TH 16.75,30.75 r90 top
TP32 "BIAS6" TestPoint_50x30-TH 29.75,16.75 r90 top
TP33 "BIAS7" TestPoint_50x30-TH 49,18.5 r90 top locked
TP34 "BIAS8" TestPoint_50x30-TH 36,34.75 r90 top
TP35 "IN5+" TestPoint_50x30-TH 19,25.5 r90 top
TP36 "IN6+" TestPoint_50x30-TH 35.5,15.25 r90 top
TP37 "IN7+" TestPoint_50x30-TH 53.5,22 r90 top locked
TP38 "IN8+" TestPoint_50x30-TH 36,40.25 r90 top
TP39 "IN5-" TestPoint_50x30-TH 14.5,29.5 r90 top
TP40 "IN6-" TestPoint_50x30-TH 29,14 r90 top
TP41 "IN7-" TestPoint_50x30-TH 50.5,16.25 r90 top
TP42 "IN8-" TestPoint_50x30-TH 39,34.75 r90 top
TP43 "D2B" TestPoint_50x30-TH 41.75,40.25 r90 top
TP44 "D1B" TestPoint_50x30-TH 14.25,23.25 r90 top
TP45 "D1B" TestPoint_50x30-TH 34.25,10.25 r90 top
TP46 "D2B" TestPoint_50x30-TH 56.75,18 r90 top
TP47 "CLKB" TestPoint_50x30-TH 41.75,34.75 r90 top
TP48 "CLKB" TestPoint_50x30-TH 11.5,27 r90 top
TP49 "CLKB" TestPoint_50x30-TH 28.25,11.5 r90 top
TP50 "CLKB" TestPoint_50x30-TH 52.25,14.5 r90 top
TP51 "GND" TestPoint_50x30-TH 16.75,24.25 r0 top
TP52 "GND" TestPoint_50x30-TH 35,12.75 r90 top
TP53 "GND" TestPoint_50x30-TH 55.25,20 r90 top
TP54 "GND" TestPoint_50x30-TH 39,40.25 r90 top
U1 "PCM1864DBTR" DBT0030A_N 36.75,52.5 r180 bottom locked
U2 "PCM1864DBTR" DBT0030A_N 35.5,23.5 r0 bottom locked
U3 "LVC1G125" DCK0005A_N 27.5,52.5 r180 top
U4 "LVC1G126" DCK0005A_N 33.75,46 r0 bottom
U5 "LVC1G125" DCK0005A_N 29.25,48 r180 bottom
U6 "LVC1G126" DCK0005A_N 29.25,45.25 r0 bottom
U7 "LVC1G125" DCK0005A_N 31.25,48 r180 top
U8 "LVC1G126" DCK0005A_N 31.25,45.25 r0 top
Y1 "9B-24.576MEEJ-B" TXC_9B 43.5,49 r270 bottom locked
ZZ1 "These assemblies are ESD sensitive, ESD precautions shall be observed." AssemblyNote -5.785,82.205 r0 top
ZZ2 "These assemblies must be clean and free from flux and all contaminants. Use of no clean flux is not acceptable." AssemblyNote -5.785,79.956 r0 top
ZZ3 "These assemblies must comply with workmanship standards IPC-A-610 Class 2, unless otherwise specified." AssemblyNote -5.785,77.707 r0 top

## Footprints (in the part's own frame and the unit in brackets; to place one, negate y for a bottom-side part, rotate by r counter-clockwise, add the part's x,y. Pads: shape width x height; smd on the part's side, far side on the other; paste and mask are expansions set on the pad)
0402L [mm] "0402 from SM-752 data"
  rect 0.6x0.5 smd: 1(-0.5,0) 2(0.5,0)
  body extent -0.55,-0.3 0.55,0.3, height 0.6
0603L [mm] "0603 from SM-752 data"
  rect 0.8x0.85 smd: 1(-0.7,0) 2(0.7,0)
  silkscreen extent -0.07,-0.33 0.07,0.33, body extent -0.87,-0.47 0.87,0.47, height 1
0805_KTR [mm] "ROHM"
  rect 0.7x1.15 smd: 1(-0.95,0) 2(0.95,0)
  silkscreen extent -0.35,-0.7 0.35,0.7, body extent -1.05,-0.67 1.05,0.67, height 0.65
AssemblyNote [mm] "Assembly Note"
BuildingFastener_MPMS_003_0005_PH [mil] "MACHINE SCREW PAN PHILLIPS M3"
  round 1 on Mech3: 0(0,0)
  body extent -118,-118 118,118, height 93
CONN_PEC04DAAN [mm] "SULLINS"
  rect 1.65x1.65 hole 1.016 mask+0: 1(-3.81,-1.27)
  round 1.65 hole 1.016 mask+0: 2(-3.81,1.27) 3(-1.27,-1.27) 4(-1.27,1.27) 5(1.27,-1.27) 6(1.27,1.27) 7(3.81,-1.27) 8(3.81,1.27)
  silkscreen extent -6.18,-2.6 5.08,2.54, body extent -5.08,-2.54 5.08,2.54, height 8.38
DBT0030A_N [mm] "TSSOP, 30-Leads, Body 7.8x4.4mm, Pitch 0.5mm, IPC Medium Density"
  oval 1.4x0.3 smd: 1(-2.95,3.5) 2(-2.95,3) 3(-2.95,2.5) 4(-2.95,2) 5(-2.95,1.5) 6(-2.95,1) 7(-2.95,0.5) 8(-2.95,0) 9(-2.95,-0.5) 10(-2.95,-1) 11(-2.95,-1.5) 12(-2.95,-2) 13(-2.95,-2.5) 14(-2.95,-3) 15(-2.95,-3.5) 16(2.95,-3.5) 17(2.95,-3) 18(2.95,-2.5) 19(2.95,-2) 20(2.95,-1.5) 21(2.95,-1) 22(2.95,-0.5) 23(2.95,0) 24(2.95,0.5) 25(2.95,1) 26(2.95,1.5) 27(2.95,2) 28(2.95,2.5) 29(2.95,3) 30(2.95,3.5)
  silkscreen extent -3.42,-3.95 1.5,3.95, body extent -3.21,-3.9 3.21,3.9, height 1.2
DCK0005A_N [mm] "SOT353, 5-Leads, Body 2x1.3mm, Pitch 0.65mm, Lead Span 2.1mm, IPC Medium Density"
  rrect25% 0.85x0.4 smd: 1(-1.125,0.65) 2(-1.125,0) 3(-1.125,-0.65) 4(1.125,-0.65) 5(1.125,0.65)
  silkscreen extent -1.48,-1.02 0.55,1.1, body extent -1.14,-1 1.14,1, height 0.95
FCC_disclaimer_stacked [mm]
Fiducial10-20 [mm]
  round 1 smd mask+0.5: 1(0,0)
  Top Copper keep-out circle w1.178: c0,0 r0.5
Keystone24438 [mil] "Standoff, Aluminium, M3x0.5mm, L 25 mm"
  round 1 on Mech4: 0(0,0)
  body extent -98,-114 98,114, height 984
Knowles_SPH1642HT5H-1 [mm] "SMD, 6-Leads, Body 3.5x2.65mm"
  rect 1.032x0.622 smd: 1(-0.342,0.884) 3(-0.342,-0.884) 4(1.866,-0.884) 6(1.866,0.884)
  rect 1.032x0.5 smd: 2(-0.342,0) 5(1.866,0)
  silkscreen extent -1.16,-1.5 2.68,1.5, body extent -1.04,-1.38 2.56,1.38, height 1.1
LED_LTST-C171 [mm] "LITE-ON"
  rect 1.2x1.2 smd: 1(-1.05,0) 2(1.05,0)
  silkscreen extent -1.6,-1 2.2,1, body extent -1.05,-0.67 1.05,0.67, height 0.8
LED_SMLP12_BLUE [mm] "Rohm Semiconductor"
  rect 0.5x0.6 smd mask+0.08: 1(-0.45,0) 2(0.45,0)
  silkscreen extent 0.92,-0.3 0.92,0.3, body extent -0.55,-0.35 0.55,0.35, height 0.25
Pb-Free_Overlay_Small [mm]
  silkscreen extent -1.16,-1.17 1.17,1.17
SNT-100-BK-G [mil] "Samtec STEP model"
  round 1 on Mech4: 0(0,0)
  body extent -100,-50 100,50, height 344
SOT-23 [mm] "SOT23, 3-Leads, Body 2.9x1.3mm, Pitch 0.95mm, Lead Span 2.5mm, IPC Medium Density"
  rrect50% 1x0.6 smd: 1(-1.2,0.95) 2(-1.2,-0.95) 3(1.2,0)
  silkscreen extent -1.62,-1.5 0.7,1.5, body extent -1.16,-1.45 1.21,1.45, height 1
Sullins_PBC02SAAN [mm] "Sullins 100mil, 1x2, 230 mil above insulator"
  rect 1.65x1.65 hole 1.016: 1(0,1.27)
  round 1.65 hole 1.016: 2(0,-1.27)
  silkscreen extent -1.37,-2.54 1.27,3.1, body extent -1.27,-2.54 1.27,2.54, height 8.38
Sullins_PPPC082LJBN-RC [mm] "Sullins Electronics"
  rect 1.5x1.5 hole 1.016 paste+0: 1(8.89,-1.27)
  round 1.5 hole 1.016 paste+0: 2(8.89,1.27) 3(6.35,-1.27) 4(6.35,1.27) 5(3.81,-1.27) 6(3.81,1.27) 7(1.27,-1.27) 8(1.27,1.27) 9(-1.27,-1.27) 10(-1.27,1.27) 11(-3.81,-1.27) 12(-3.81,1.27) 13(-6.35,-1.27) 14(-6.35,1.27) 15(-8.89,-1.27) 16(-8.89,1.27)
  silkscreen extent -10.51,-11.57 10.54,-1.14, body extent -10.41,-11.37 10.41,1.58, height 5.08
Sullins_PxC02DAAN [mm] "Header, 2.54mm, 2x2, TH"
  rect 1.7x1.7 hole 1.2: 1(-1.27,1.27)
  round 1.7 hole 1.2: 2(1.27,1.27) 3(-1.27,-1.27) 4(1.27,-1.27)
  silkscreen extent -2.61,-2.8 2.61,3.2, body extent -2.61,-2.8 2.61,2.8, height 8.58
TestPoint_50x20-TH [mil] "Thru Hole Test Point, 50mil Pad, 20mil Drill"
  round 50 hole 20: 1(0,0)
  silkscreen extent -35,-35 35,35, body extent -25,-25 25,25, height 50
TestPoint_50x30-TH [mil] "Thru Hole Test Point, 50mil Pad, 20mil Drill"
  round 50 hole 30: 1(0,0)
  silkscreen extent -35,-35 35,35, body extent -25,-25 25,25, height 50
TI_Stacked_Overlay_Small [mm]
  silkscreen extent -10.63,-2.49 10.63,2.49
TSW-110-07-G-D [mm] "Samtec 100mil, 2x10, 230 mil above insulator"
  rrect6% 1.65x1.65 hole 1.016: 1(-11.43,-1.27)
  round 1.65 hole 1.016: 2(-11.43,1.27) 3(-8.89,-1.27) 4(-8.89,1.27) 5(-6.35,-1.27) 6(-6.35,1.27) 7(-3.81,-1.27) 8(-3.81,1.27) 9(-1.27,-1.27) 10(-1.27,1.27) 11(1.27,-1.27) 12(1.27,1.27) 13(3.81,-1.27) 14(3.81,1.27) 15(6.35,-1.27) 16(6.35,1.27) 17(8.89,-1.27) 18(8.89,1.27) 19(11.43,-1.27) 20(11.43,1.27)
  silkscreen extent -13.72,-2.54 12.7,2.54, body extent -12.7,-2.54 12.7,2.54, height 8.38
TXC_9B [mm] "TH, 2-Leads, Body 11.5x5mm, Pin Spacing 4.88mm"
  round 1.35 hole 0.85: 1(-2.44,0) 2(2.44,0)
  silkscreen extent -5.75,-2.5 5.75,2.5, body extent -5.75,-2.5 5.75,2.5, height 3.68

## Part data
C1 C2 C3 C4 C5 C6 C7 C17 C23 C25 C29 C31 C37 C39: "CAP, CERM, 0.1 µF, 16 V, +/- 10%, X7R, 0603"
C8 C9 C10 C11 C12 C13 C14 C15 C16 C18 C19 C20 C21 C22 C30 C32 C33 C34 C35 C36: "CAP, CERM, 10 µF, 10 V, +/- 10%, X7R, 0805"
C24 C26 C38 C40: "CAP, CERM, 1 µF, 16 V, +/- 10%, X7R, 0603"
C27 C28: "CAP, CERM, 18 pF, 50 V, +/- 5%, C0G/NP0, 0603"
D1: library part LTST-C171GKT, "LED, Green, SMD"
D2 D3: library part SMLP12BC7TT86, "LED, Blue, SMD"
FID1 FID2 FID3: "Fiducial mark.  There is nothing to buy or mount."
H1 H2 H3 H4: library part "MPMS 003 0005 PH", "MACHINE SCREW PAN PHILLIPS M3 5mm"
H5 H6 H7 H8: "Standoff, Hex,25mm Length, M3, Aluminum"
J1: library part PEC04DAAN, "Header, 100mil, 4x2, Tin, TH"
J2 J4: library part PBC02SAAN, "Header, 100mil, 2x1, Gold, TH"
J3: library part PPPC082LJBN-RC, "Receptacle, 100mil, 8x2, Gold, R/A, TH"
J5: library part TSW-110-07-G-D, "Header, 100mil, 10x2, Gold, TH"
J6: "Header, 2.54mm, 2x2, Gold, TH"
J7 J8: library part JMP2-PBC02SAAN, "Header, 100mil, 2x1, Gold, TH"
Logo1: library part TI_Logo, "Texas Instrument Corporate Signature"
Logo2: library part Pb-Free
Logo3: library part FCC_disclaimer, "FCC_disclaimer"
MIC1 MIC2 MIC3 MIC4 MIC5 MIC6 MIC7 MIC8: "Wide Bandwidth, Low Noise, Precision Top Port SiSonic Microphone, SMD"
Q1 Q2: library part "MMBT2222A, Fairchild Semiconductor", "Transistor, NPN, 40 V, 0.15 A, SOT-23"
R1 R2 R3 R4 R6 R7 R8 R9 R10 R11 R12 R13 R16 R17 R19 R21 R40 R41 R42 R43 R45 R46 R49 R50 R51 R52 R54 R55 R56 R57 R59 R60 R61 R62: "RES, 49.9, 1%, 0.063 W, 0402"
R5: "RES, 10.0 k, 1%, 0.1 W, 0603"
R14 R15 R27 R28 R29 R30 R36 R37 R38 R39: "RES, 2.21 k, 1%, 0.063 W, 0402"
R18: "RES, 360, 5%, 0.063 W, 0402"
R20 R53: "RES, 100, 1%, 0.1 W, 0402"
R22 R23 R24 R25 R26 R31 R32 R33 R34 R35 R44 R48: "RES, 0, 5%, 0.1 W, 0603"
R47 R58: "RES, 2.15 k, 1%, 0.063 W, 0402"
SH1 SH2 SH3 SH4: "Shunt, 100mil, Gold plated, Black"
TP1 TP2: library part TestPoint_50x20-TH, "Test Point, 50x20mils, TH"
TP3 TP4 TP5 TP6 TP7 TP8 TP9 TP10 TP11 TP12 TP13 TP14 TP15 TP16 TP17 TP18 TP19 TP20 TP21 TP22 TP23 TP24 TP25 TP26 TP27 TP28 TP29 TP30 TP31 TP32 TP33 TP34 TP35 TP36 TP37 TP38 TP39 TP40 TP41 TP42 TP43 TP44 TP45 TP46 TP47 TP48 TP49 TP50 TP51 TP52 TP53 TP54: library part TestPoint_50x30-TH, "Test Point, 50x30mils, TH"
U1 U2: "Universal Microphone to 2VRMS Analog input, 24-Bit, 192 kHz Stereo Front-End, DBT0030A"
U3 U5 U7: library part SN74LVC1G125DCKR, "Single Bus Buffer Gate With 3-State Output, DCK0005A"
U4 U6 U8: library part SN74LVC1G126DCKR, "Single Bus Buffer Gate With 3-State Output, DCK0005A"
Y1: "Crystal, 24.576MHz, 18 pF, TH"
ZZ1 ZZ2 ZZ3: library part AssemblyNote

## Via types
v1: diameter 0.635, hole 0.254, Top Copper to Bottom Copper, tented both sides, 98 vias
v2: diameter 0.762, hole 0.381, Top Copper to Bottom Copper, 7 vias
v3: diameter 6, hole 3.25, Top Copper to Bottom Copper, tented both sides, 4 vias
v4: diameter 0.75, hole 0.38, Top Copper to Bottom Copper, 1 vias

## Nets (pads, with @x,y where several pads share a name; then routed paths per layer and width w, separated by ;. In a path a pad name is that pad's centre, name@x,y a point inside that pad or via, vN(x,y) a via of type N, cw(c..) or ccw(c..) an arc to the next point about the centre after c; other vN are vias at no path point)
3.3V: C1.2 C2.2 C3.2 C4.2 C5.2 C6.2 D2.1 D3.1 J4.1 J5.16 R5.2 R14.1 R15.1 R18.2 R22.1 R31.1 R44.1 R48.1 TP2.1 U2.25 U3.5 U4.5 U5.5 U6.5 U7.5 U8.5 | length 49.5
  Top Copper w0.25: v1(7,46.5) R14.1@7.75,46.5 ; C2.2@24.95,51.75 C2.2@25,51.8 ; v1(25,52.75) C2.2@25,51.8 ; U3.5@26.375,51.85 25.05,51.85 C2.2@25,51.8 ; v1(26.625,49.75) 27.25,49.75 28.95,48.05 C6.2@28.95,47.25 29.05,47.35 U7.5@30.125,47.35 ; R15.1@30.75,54.5 31.75,54.5 v1(32.25,54) 33,53.25 R22.1@33.05,53.25 ; U8.5@32.375,45.9 33.8,45.9 C1.2@34,45.7 34.075,45.625 v1(36,45.625) ; R44.1@35.45,19.375 35.5,19.325 v1(35.5,18) 38,18 40,20 v1(40,22.5) ; v1(37.5,67) 37.5,70.45 D2.1@37.55,70.5 ; R48.1@38,27.95 v1(38,29) ; R31.1@39.75,48.825 39.825,48.75 v1(41.25,48.75) ; D3.1@45.45,8 v1(46.5,8)
  Copper Layer 4 w2: J4.1@11.395,17.875 13.625,20.105 13.625,20.375 ; 27,67.125 TP2.1@27,71.375
  Bottom Copper w0.25: v1(26.625,49.75) 26.625,48.825 C3.2@26.7,48.75 26.8,48.65 U5.5@28.125,48.65 ; v1(28,41) R5.2@28,42.05 ; v1(29.25,43.5) 30.2,43.5 C5.2@30.25,43.45 30.25,44.475 U6.5@30.375,44.6 ; v1(34.875,43) 34.875,43.95 C4.2@34.925,44 34.875,44.05 U4.5@34.875,45.35 ; U2.25@38.45,22.5 v1(40,22.5) ; v1(48.75,9.25) R18.2@49.75,9.25
3.3V-USB: J3.15 J3.16 J4.2 | length 13.8
  Top Copper w1: J4.2@8.875,17.875 8.875,27.255 J3.15@10.23,28.61 J3.16@12.77,28.61
AVDD1: C7.2 C8.2 R22.2 U1.8 | length 5.6
  Top Copper w0.25: R22.2@34.45,53.25 34.5,53.3 C8.2@35.75,53.3 37.2,53.3 38,52.5 v1(38.375,52.5)
  Bottom Copper w0.25: v1(38.375,52.5) U1.8@39.7,52.5
AVDD2: C29.2 C30.2 R44.2 U2.8 | length 5.6
  Top Copper w0.25: v1(34,23.5) 34,22.425 C29.2@34.05,22.375 C30.2@34.05,20.875 R44.2@34.05,19.375
  Bottom Copper w0.25: U2.8@32.55,23.5 v1(34,23.5)
BCK: R2.1 R8.1 R11.2 R13.1 U5.4 U6.2 | length 61
  Copper Layer 3 w0.25: v1(26.75,46.25) 26.75,44.25 29.5,41.5 29.5,40 28.25,38.75 v1(28.25,36.5) 28.25,35.75 29,35 30.5,35 33.5,32 37,32 40.5,28.5 45.5,28.5 46.875,29.875 55.375,29.875 v1(56.5,28.75)
  Bottom Copper w0.25: R11.2@27,34 28.25,35.25 v1(28.25,36.5) ; U6.2@28.125,45.25 27.125,45.25 26.75,45.625 v1(26.75,46.25) R8.1@26.75,47.375 28.1,47.375 U5.4@28.125,47.35 ; R13.1@55.5,28.75 v1(56.5,28.75) 58.5,26.75 R2.1@63.5,26.75
BCKA: U1.17 U5.2 U6.4 | length 7.4
  Bottom Copper w0.25: U6.4@30.375,45.9 31.15,45.9 31.25,46 31.25,48 ; U5.2@30.375,48 31.25,48 ; U1.17@33.8,49.5 32.75,49.5 32.375,49.125 32.375,48.375 32,48 31.25,48
BCKB: R11.1 U2.17 | length 15.3
  Bottom Copper w0.25: R11.1@27,33 27,32 28.375,30.625 34.5,30.625 37.25,27.875 37.25,26.875 37.625,26.5 U2.17@38.45,26.5
BCLK-I2X: J3.7 R8.2 | length 21
  Bottom Copper w0.25: J3.7@10.23,38.77 11.46,40 14,40 15.125,41.125 22.75,41.125 24.5,42.875 24.5,46.125 R8.2@25.75,47.375
BCLK-MINIDSP: J5.4 R13.2 | length 2.3
  Bottom Copper w0.25: J5.4@52.27,28.61 54.36,28.61 R13.2@54.5,28.75
BCLK-PSIA: J1.3 R2.2 | length 2.2
  Bottom Copper w0.25: R2.2@64.5,26.75 64.52,26.73 J1.3@66.73,26.73
BIAS_MIC1: MIC1.6 R27.2 TP7.1 | length 3.7
  Top Copper w0.25: MIC1.6@59.625,36.625 MIC1.6@59.634,36.616 59.75,36.5 TP7.1@59.75,34.75
  Bottom Copper w0.25: R27.2@58,34.75 TP7.1@59.75,34.75
BIAS_MIC2: MIC2.6 R28.2 TP8.1 | length 4.2
  Top Copper w0.25: MIC2.6@51.991,54.254 TP8.1@53.5,53
  Bottom Copper w0.25: TP8.1@53.25,53 TP8.1@53.5,53 R28.2@55.5,53
BIAS_MIC3: MIC3.6 R29.2 TP9.1 | length 3.6
  Top Copper w0.25: MIC3.6@33.436,59.276 TP9.1@35.25,59.75
  Bottom Copper w0.25: TP9.1@35.25,59.75 R29.2@37,59.75
BIAS_MIC4: MIC4.6 R30.2 TP10.1 | length 6
  Top Copper w0.25: MIC4.6@17.941,47.9 17.75,48 TP10.1@18.5,49.75 19.5,50.75 v1(19.5,52.5)
  Bottom Copper w0.25: v1(19.5,52.5) R30.2@19.5,53.25
BIAS_MIC5: MIC5.6 R36.2 TP31.1 | length 12.9
  Top Copper w0.25: MIC5.6@17.175,28.692 16.967,29.25 16.75,29.467 TP31.1@16.75,30.75 19,33 R36.2@26.5,33
BIAS_MIC6: MIC6.6 R37.2 TP32.1 | length 3.6
  Top Copper w0.25: R37.2@29.75,18.25 TP32.1@29.75,16.75 MIC6.6@31.714,16.117
BIAS_MIC7: MIC7.6 R38.2 TP33.1 | length 28.2
  Top Copper w0.25: v1(45,30) 45,22.5 TP33.1@49,18.5 50.5,19.75 MIC7.6@50.61,19.644
  Bottom Copper w0.25: R38.2@33.5,33.5 35,33.5 36,32.5 39.625,32.5 40.875,31.25 43.75,31.25 v1(45,30)
BIAS_MIC8: MIC8.6 R39.2 TP34.1 | length 4.8
  Top Copper w0.25: MIC8.6@35.634,36.616 35.884,36.616 36,36.5 TP34.1@36,34.75
  Bottom Copper w0.25: R39.2@33.5,34.375 33.875,34.75 TP34.1@36,34.75
DATA1: J6.1 J6.3 R4.1 R7.1 R17.1 | length 61.4
  Top Copper w0.25: J6.3@21.27,36.73 J6.1@21.27,39.27 24.375,42.375 28.625,42.375 30.5,40.5 33.375,40.5 34.563,41.688 35.312,41.688 35.625,42 v1(38,42) ; v1(45.375,42.5) 45.375,39.625 47.5,37.5 54.5,37.5 56.5,35.5 v1(56.5,33.75)
  Copper Layer 3 w0.25: v1(38,42) 38.375,41.625 40.875,41.625 41.75,42.5 v1(45.375,42.5)
  Bottom Copper w0.25: R7.1@16.5,38 20,38 J6.3@21.27,36.73 ; R17.1@55.5,33.75 v1(56.5,33.75) 58.5,31.75 R4.1@63.5,31.75
DATA1-MINIDSP: J5.8 R17.2 | length 2.3
  Bottom Copper w0.25: J5.8@52.27,33.69 54.44,33.69 R17.2@54.5,33.75
DATA2-MINIDSP: J5.10 R19.2 | length 2.5
  Bottom Copper w0.25: J5.10@52.27,36.23 54.73,36.23 R19.2@54.75,36.25
DATA3-MINIDSP: J5.12 R45.2 | length 5.3
  Bottom Copper w0.25: R45.2@47.5,40 51.04,40 J5.12@52.27,38.77
DATA4-MINIDSP: J5.14 R46.2 | length 20.8
  Copper Layer 3 w0.25: v1(41,30) 43,32 44.875,32 47,34.125 47,39 48,40 50.96,40 J5.14@52.27,41.31
  Bottom Copper w0.25: R46.2@41,28 v1(41,30)
DATA-I2X: J3.9 R7.2 | length 6
  Bottom Copper w0.25: J3.9@10.23,36.23 11.5,37.5 15,37.5 R7.2@15.5,38
DATA-PSIA: J1.7 R4.2 | length 2.3
  Bottom Copper w0.25: R4.2@64.5,31.75 64.56,31.81 J1.7@66.73,31.81
DMCLKA: R49.1 R50.1 R51.1 R52.1 U1.20 | length 115.9
  Top Copper w0.25: v1(16.5,52.75) 17.75,54 21,54 21.625,53.375 21.625,51 22.5,50.125 24.75,50.125 25.625,51 v1(27.5,51)
  Copper Layer 3 w0.25: v1(23,66) 28.875,66 30.25,64.625 v1(31,64.625) 31.75,65.375 31.75,66.625 32.75,67.625 34.625,67.625 38.25,64 v1(40,64)
  Bottom Copper w0.25: R52.1@15.25,52.75 v1(16.5,52.75) 16.5,54.5 23,61 v1(23,66) ; v1(27.5,51) 28.125,51.625 32.25,51.625 32.875,51 U1.20@33.8,51 ; v1(31,64.625) 31.875,64.625 R51.1@32,64.75 ; v1(40,64) 56,64 60,60 R50.1@60,57.5 60,56.5 62.875,53.625 68.625,53.625 70.75,51.5 70.75,39.75 68,37 R49.1@68,35.75
DMCLKB: R59.1 R60.1 R61.1 R62.1 U2.20 | length 85.6
  Top Copper w0.25: v1(29.375,9.25) 31.375,9.25 31.625,9 33.375,9 33.75,8.625 42.625,8.625 v1(48.5,14.5)
  Copper Layer 3 w0.25: v1(12.5,24.75) 13.75,26 17,26 19,28 28,28 30.25,25.75 35.25,25.75 v1(36,25) ; v1(46.5,23.5) 46.5,16.5 v1(48.5,14.5)
  Bottom Copper w0.25: R59.1@11.5,24.75 v1(12.5,24.75) ; R60.1@28.25,9.25 v1(29.375,9.25) ; v1(36,25) U2.20@38.45,25 ; U2.20@38.5,25 41.375,25 41.75,25.375 43.625,25.375 45.5,23.5 v1(46.5,23.5) 46.5,31.375 45.375,32.5 R62.1@41.75,32.5 ; v1(48.5,14.5) R61.1@49.75,14.5
DMIN1A/INTA: J5.20 R40.1 R41.1 U1.21 | length 57.5
  Copper Layer 3 w0.25: v1(37,52) 37,54.25 38.125,55.375 43.25,55.375 46.625,52 50.75,52 52.27,50.48 J5.20@52.27,48.93 55.93,48.93 v1(60,53)
  Bottom Copper w0.25: U1.21@33.8,51.5 34.75,51.5 35,51.25 36.25,51.25 v1(37,52) ; R41.1@55,60.25 55.875,59.375 55.875,57.125 v1(60,53) 63.875,49.125 65.875,49.125 66.75,48.25 66.75,45 66.5,44.75 R40.1@66.5,43.5
DMIN1B/INTB: J5.19 R54.1 R55.1 U2.21 | length 76.6
  Top Copper w0.25: v1(36.5,23.5) 37.5,23.5 39.5,25.5 39.5,32 40.5,33 v1(40.5,43)
  Copper Layer 3 w0.25: v1(15.25,20.875) 33.416,20.875 36.041,23.5 v1(36.5,23.5) 38.041,23.5 38.5,23.041 38.5,11.25 v1(37.5,10.25)
  Bottom Copper w0.25: v1(15.25,20.875) R54.1@15.25,21.75 ; R55.1@36.5,10.25 v1(37.5,10.25) ; v1(36.5,23.5) 37.5,24.5 U2.21@38.45,24.5 ; v1(40.5,43) 41.5,44 45,44 47,46 47,48 47.93,48.93 J5.19@49.73,48.93
DMIN2A/SCKO: R42.1 R43.1 U1.22 U3.2 | length 20.5
  Top Copper w0.25: v1(26.75,62.5) 27.5,61.75 27.5,56 v1(27.5,52.5) U3.2@28.625,52.5 30.209,52.5 30.709,52 v1(35.25,52)
  Bottom Copper w0.25: v1(26.75,62.5) R42.1@26.75,63.25 ; U1.22@33.8,52 v1(35.25,52)
DMIN2B: R56.1 R57.1 U2.22 | length 53.2
  Top Copper w0.25: v1(44,41.25) 44,39 48,35 53.5,35 56.125,32.375 57.125,32.375 58,31.5 58,22.5 v1(56.75,21.25)
  Bottom Copper w0.25: U2.22@38.45,24 42.875,24 44.875,22 50,22 52,24 54,24 v1(56.75,21.25) R56.1@56.75,20.25 ; R57.1@44,40.25 v1(44,41.25)
DOUT1A: J6.2 U1.18 | length 24.5
  Copper Layer 3 w0.25: J6.2@18.73,39.27 18.73,44.855 21.875,48 27,48 28,49 28,50.125 29.125,51.25 30.75,51.25 v1(31.5,50.5)
  Bottom Copper w0.25: v1(31.5,50.5) 32.375,50.5 32.875,50 U1.18@33.8,50
DOUT1B: J6.4 R19.1 U2.18 | length 74.8
  Top Copper w0.25: J6.4@18.73,36.73 18.73,35.52 19.5,34.75 29,34.75 31.25,37 31.25,37.625 v1(32,38.375) ; v1(37.5,43.5) 38.75,43.5 39.5,44.25 46.25,44.25 48,42.5 48,40.875 48.875,40 54,40 v1(54.5,39.5)
  Copper Layer 3 w0.25: v1(32,38.375) 32,38.875 34.875,41.75 35.75,41.75 v1(37.5,43.5)
  Bottom Copper w0.25: J6.4@18.73,36.73 18.73,33.27 22.5,29.5 33.75,29.5 37.25,26 U2.18@38.45,26 ; v1(54.5,39.5) 55.75,38.25 R19.1@55.75,36.25
DOUT2A: R45.1 U1.19 | length 20.2
  Copper Layer 3 w0.25: v1(35.875,49) 38.375,46.5 39,46.5 41,44.5 45.5,44.5 47,43 47,41.5 v1(46.5,41)
  Bottom Copper w0.25: U1.19@33.8,50.5 35.5,50.5 35.875,50.125 v1(35.875,49) ; R45.1@46.5,40 v1(46.5,41)
DOUT2B: R46.1 U2.19 | length 3.4
  Bottom Copper w0.25: U2.19@38.45,25.5 40.125,25.5 41,26.375 R46.1@41,26.875
DVDD1: C17.2 C18.2 R31.2 U1.13 U1.14 | length 5.7
  Top Copper w0.25: v1(38.5,50) 38.5,48.925 C17.2@38.45,48.875 C18.2@38.45,47.375 38.5,47.425 R31.2@39.75,47.425
  Bottom Copper w0.25: v1(38.5,50) U1.13@39.7,50 U1.14@39.7,49.5
DVDD2: C31.2 C32.2 R48.2 U2.13 U2.14 | length 6
  Top Copper w0.25: v1(34,26.5) 34.95,26.5 C31.2@35,26.55 36.45,26.55 C32.2@36.5,26.5 37.95,26.5 R48.2@38,26.55
  Bottom Copper w0.25: U2.13@32.55,26 U2.14@32.55,26.5 v1(34,26.5)
GND: C1.1 C2.1 C3.1 C4.1 C5.1 C6.1 C7.1 C8.1 C17.1 C18.1 C23.1 C24.2 C25.1 C26.2 C27.2 C28.2 C29.1 C30.1 C31.1 C32.1 C37.1 C38.2 C39.1 C40.2 D1.2 J1.2 J1.4 J1.6 J1.8 J2.2 J3.4 J3.6 J3.8 J3.10 J3.12 J5.1 J5.3 J5.5 J5.7 J5.9 J5.11 J5.13 J5.17 MIC1.1 MIC1.2 MIC1.3 MIC1.5 MIC2.1 MIC2.2 MIC2.3 MIC2.5 MIC3.1 MIC3.2 MIC3.3 MIC3.5 MIC4.1 MIC4.2 MIC4.3 MIC4.5 MIC5.1 MIC5.2 MIC5.3 MIC5.5 MIC6.1 MIC6.2 MIC6.3 MIC6.5 MIC7.1 MIC7.2 MIC7.3 MIC7.5 MIC8.1 MIC8.2 MIC8.3 MIC8.5 Q1.2 Q2.2 R23.2 R24.2 R25.2 R26.2 R32.2 R33.2 R34.2 R35.2 TP1.1 TP5.1 TP6.1 TP27.1 TP28.1 TP29.1 TP30.1 TP51.1 TP52.1 TP53.1 TP54.1 U1.7 U1.12 U1.25 U2.7 U2.12 U3.3 U4.3 U5.3 U6.3 U7.3 U8.3 | length 20
  Top Copper w0.25: C40.2@31.5,23.5 31.55,23.55 C39.1@32.875,23.55 ; C31.1@35,27.95 35.825,27.95 C32.1@36.25,28.375 ; C29.1@35.5,22.375 35.5,21.325 C30.1@35.95,20.875 ; v2(36.75,37.5) MIC8.2@37.842,37.5 ; C25.1@39.5,50.05 40.7,50.05 C26.2@40.75,50 ; v2(60.75,37.5) MIC1.2@61.842,37.5
  Bottom Copper w0.25: v1(30.375,46.625) U5.3@30.375,47.35 ; 31.125,25.375 31.25,25.5 U2.12@32.55,25.5 33.5,25.5 33.75,25.75 ; 31.375,23.375 31.75,23 U2.7@32.55,23 33.375,23 33.625,22.75 ; U1.25@33.8,53.5 35.125,53.5 35.5,53.875 ; U1.12@39.7,50.5 40.875,50.5 41.25,50.125 ; U1.7@39.7,53 40.75,53 41,52.75 ; v2(60.75,37.5) R23.2@61.8,37.5
  other v1: 36.625,30.125
  other v2: 32.325,14.85 16.575,27.425 16.575,47.575 51.987,55.666 32.325,60.15
  other v3: 15.5,12 60.875,13.125 64.5,57.625 17.5,64.75
  other v4: 51.975,19.35
LRCK: R3.1 R6.1 R16.1 R21.2 U7.4 U8.2 | length 74.8
  Top Copper w0.25: R6.1@27.5,44.5 28.25,45.25 U8.2@30.125,45.25 30.875,45.25 31.25,44.875 31.25,42.75 v1(32,42) ; v1(29.5,49.5) 29.5,49.125 29.975,48.65 U7.4@30.125,48.65 ; v1(33.5,28) v1(33.5,36) ; v1(50,24) 53,24 54.5,25.5 54.5,30 55.5,31 v1(56.5,31)
  Copper Layer 3 w0.25: v1(29.5,49.5) 29.5,45.75 30.75,44.5 30.75,43.25 v1(32,42) ; v1(30,37.5) 30.5,37 33,37 33.5,36.5 v1(33.5,36) ; v1(33.5,28) 35.5,28 38,25.5 47.5,25.5 48.25,24.75 49.25,24.75 v1(50,24)
  Bottom Copper w0.25: R21.2@30,36.5 v1(30,37.5) 30,39 32,41 v1(32,42) ; R16.1@55.5,31 v1(56.5,31) 58.25,29.25 R3.1@63.5,29.25
LRCKA: U1.16 U7.2 U8.4 | length 8.2
  Top Copper w0.25: v1(32.375,43.687) U8.4@32.375,44.6 ; U7.2@32.375,48 v1(33.75,48)
  Copper Layer 3 w0.25: v1(32.375,43.687) 33.75,45.062 v1(33.75,48)
  Bottom Copper w0.25: v1(33.75,48) 33.75,48.95 U1.16@33.8,49
LRCKB: R21.1 U2.16 | length 19.4
  Bottom Copper w0.25: R21.1@30,35.5 30,35 28.5,33.5 28.5,32.5 29.25,31.75 35,31.75 35.5,31.25 38.25,31.25 39.5,30 39.5,27.5 39,27 U2.16@38.45,27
